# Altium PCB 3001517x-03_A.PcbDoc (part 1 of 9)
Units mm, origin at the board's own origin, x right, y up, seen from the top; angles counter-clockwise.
Board outline 100 x 72 mm, 10 copper layers (Top, GND_2, Signal_3, Signal_4, PWR_5, GND_6, Signal_7, Signal_8, GND_9, Bottom), stack 1.6 mm thick; 602 components, 497 nets, 2372 pads, 1602 vias.
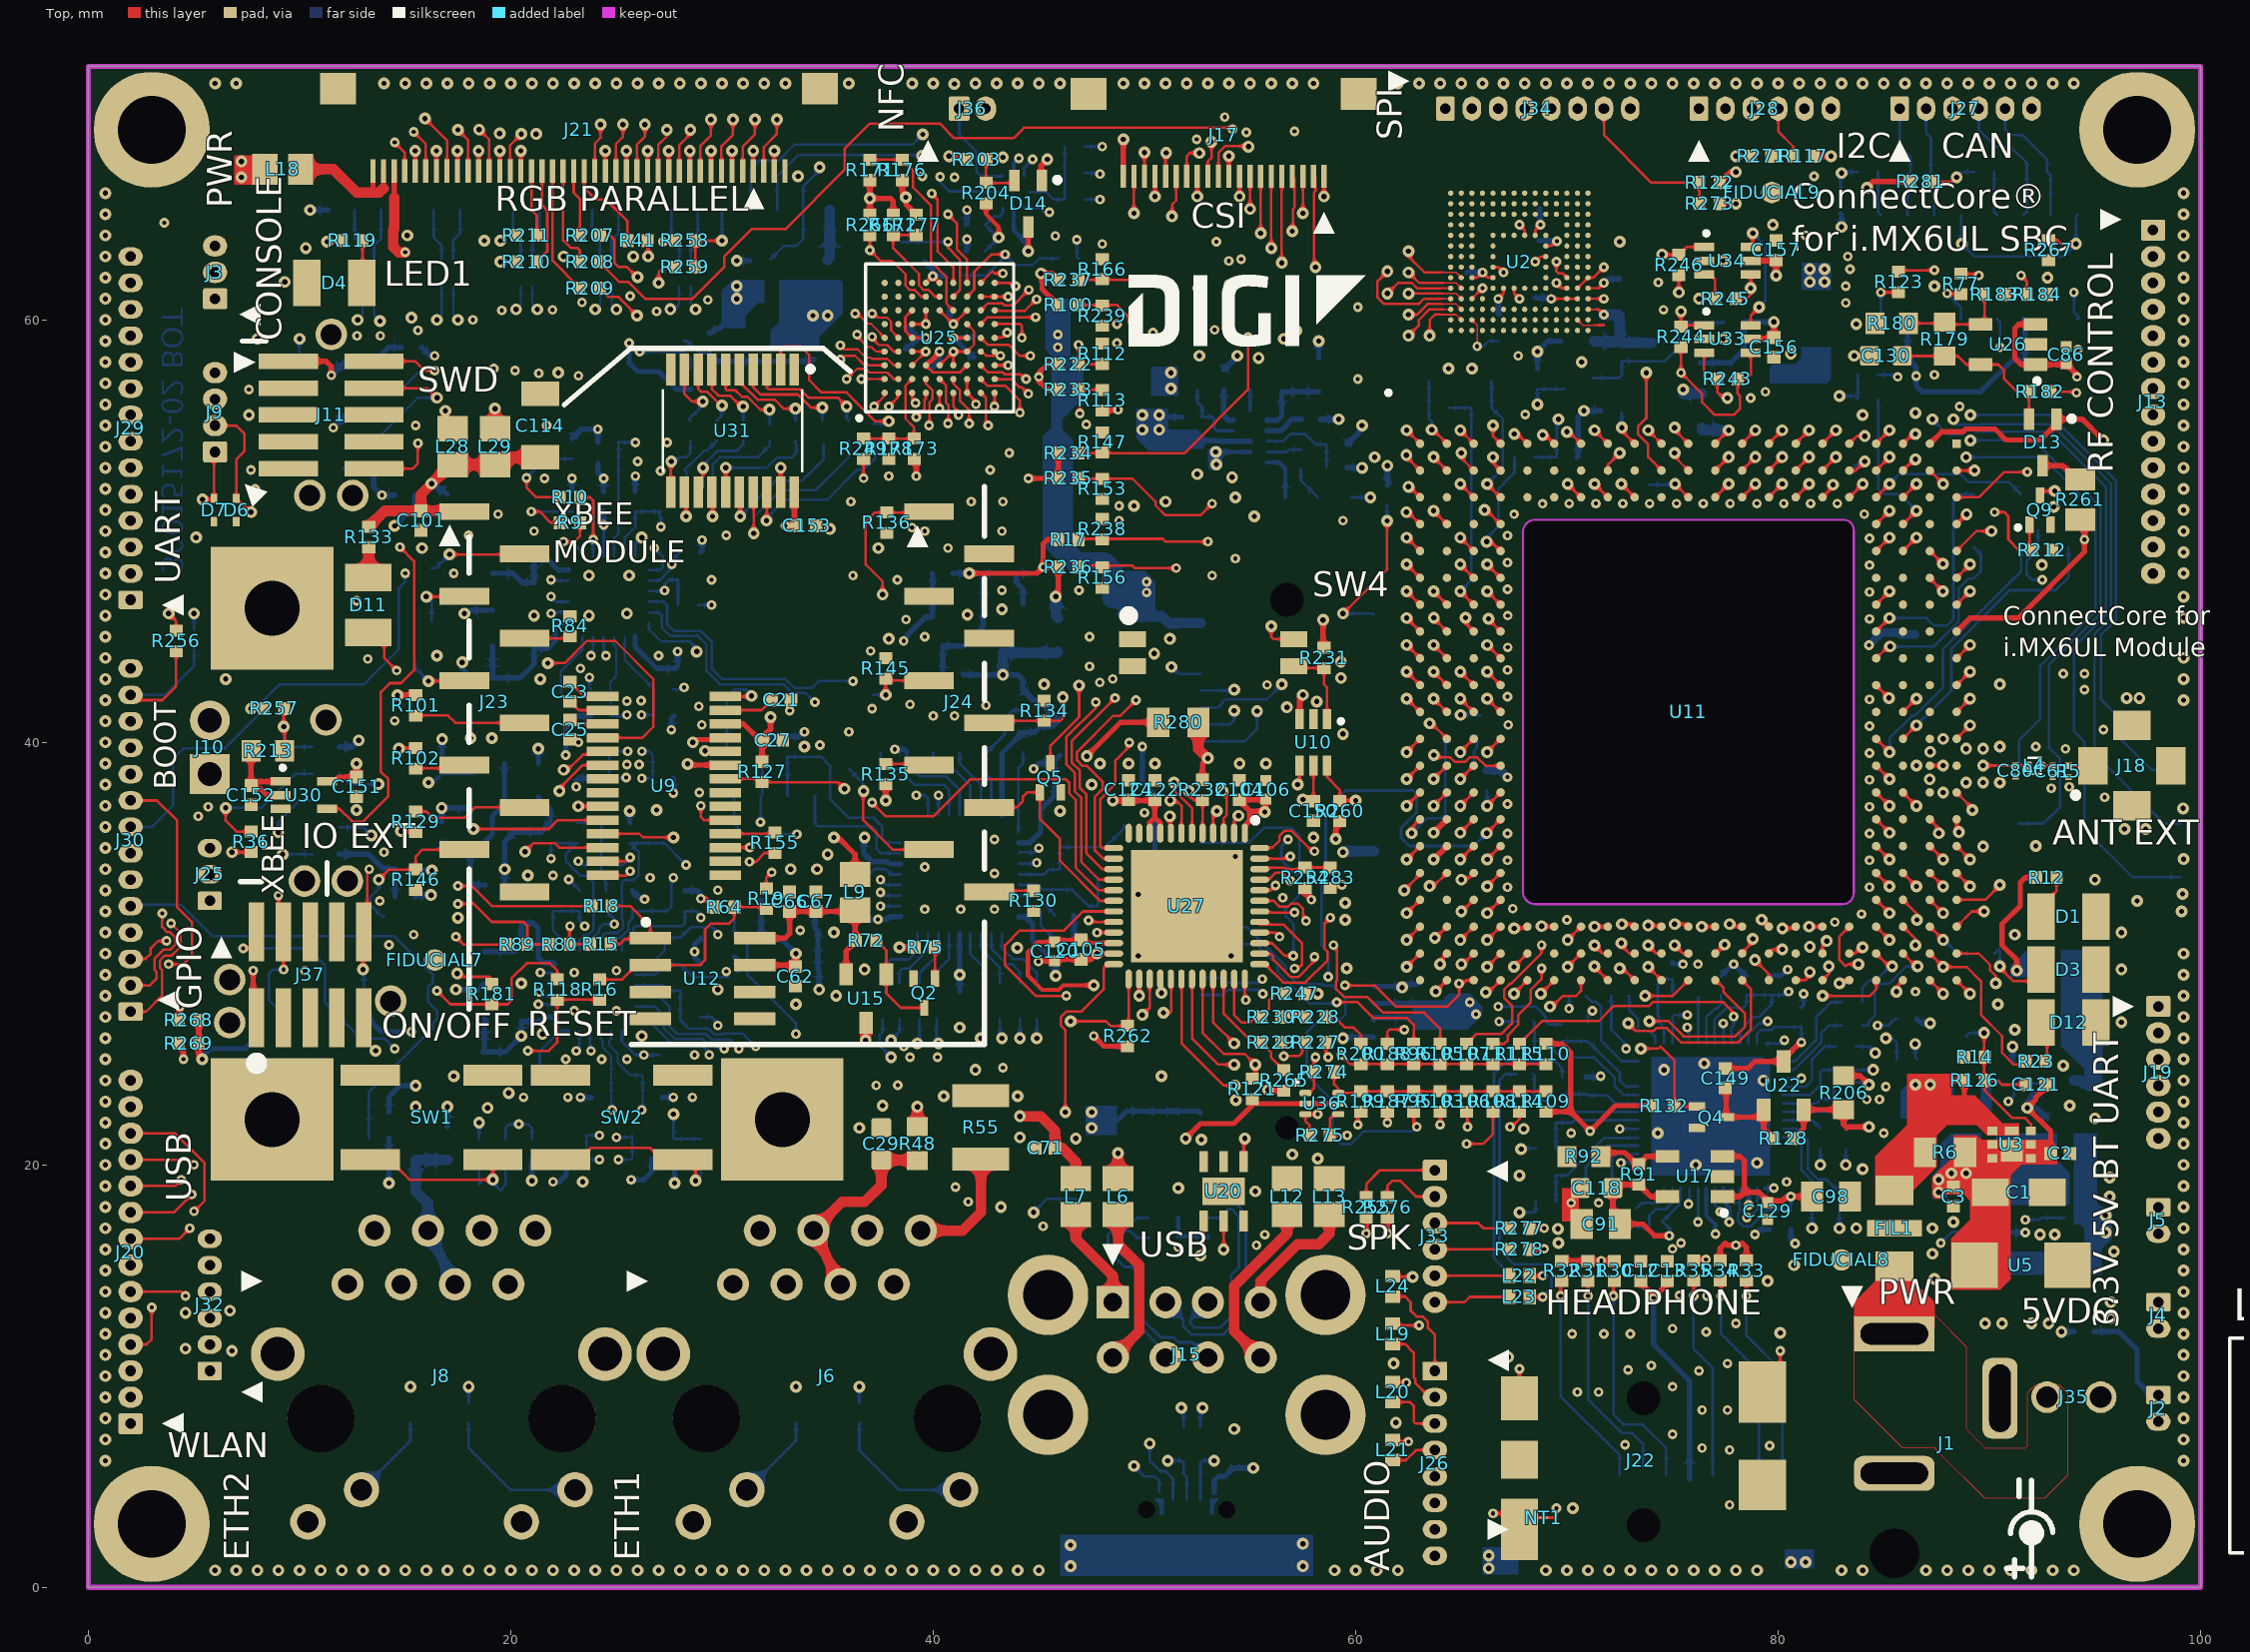
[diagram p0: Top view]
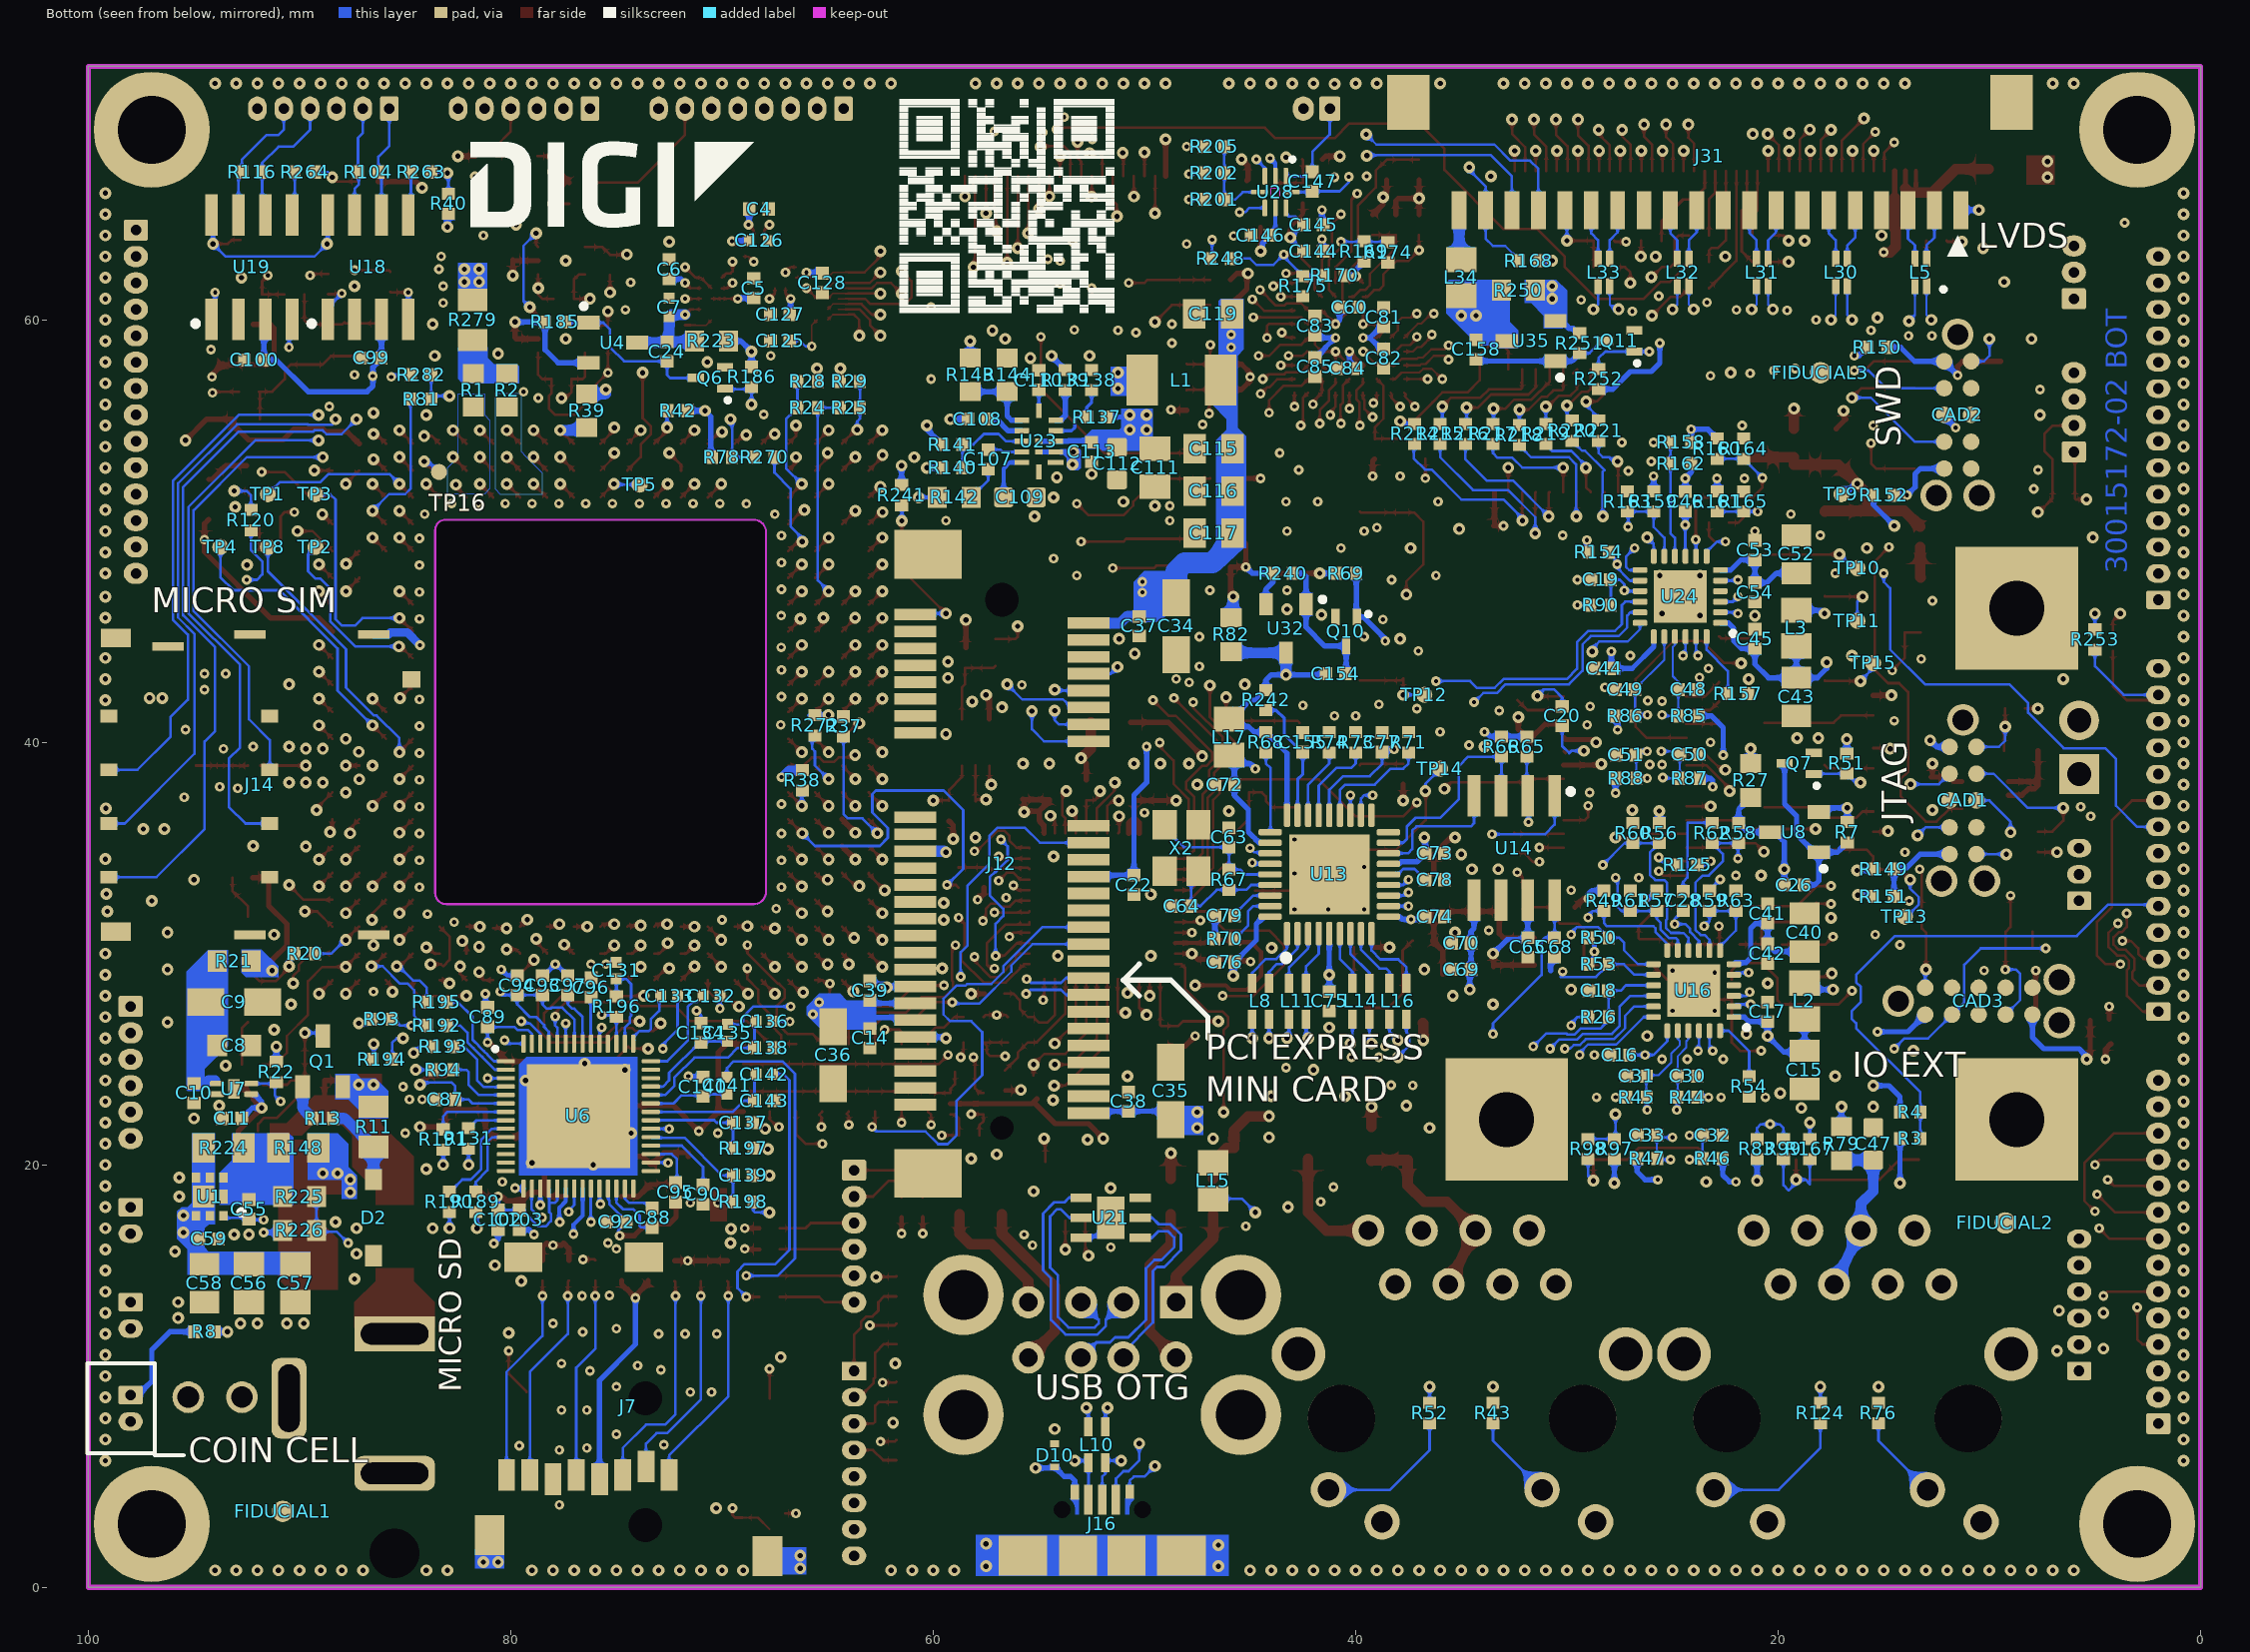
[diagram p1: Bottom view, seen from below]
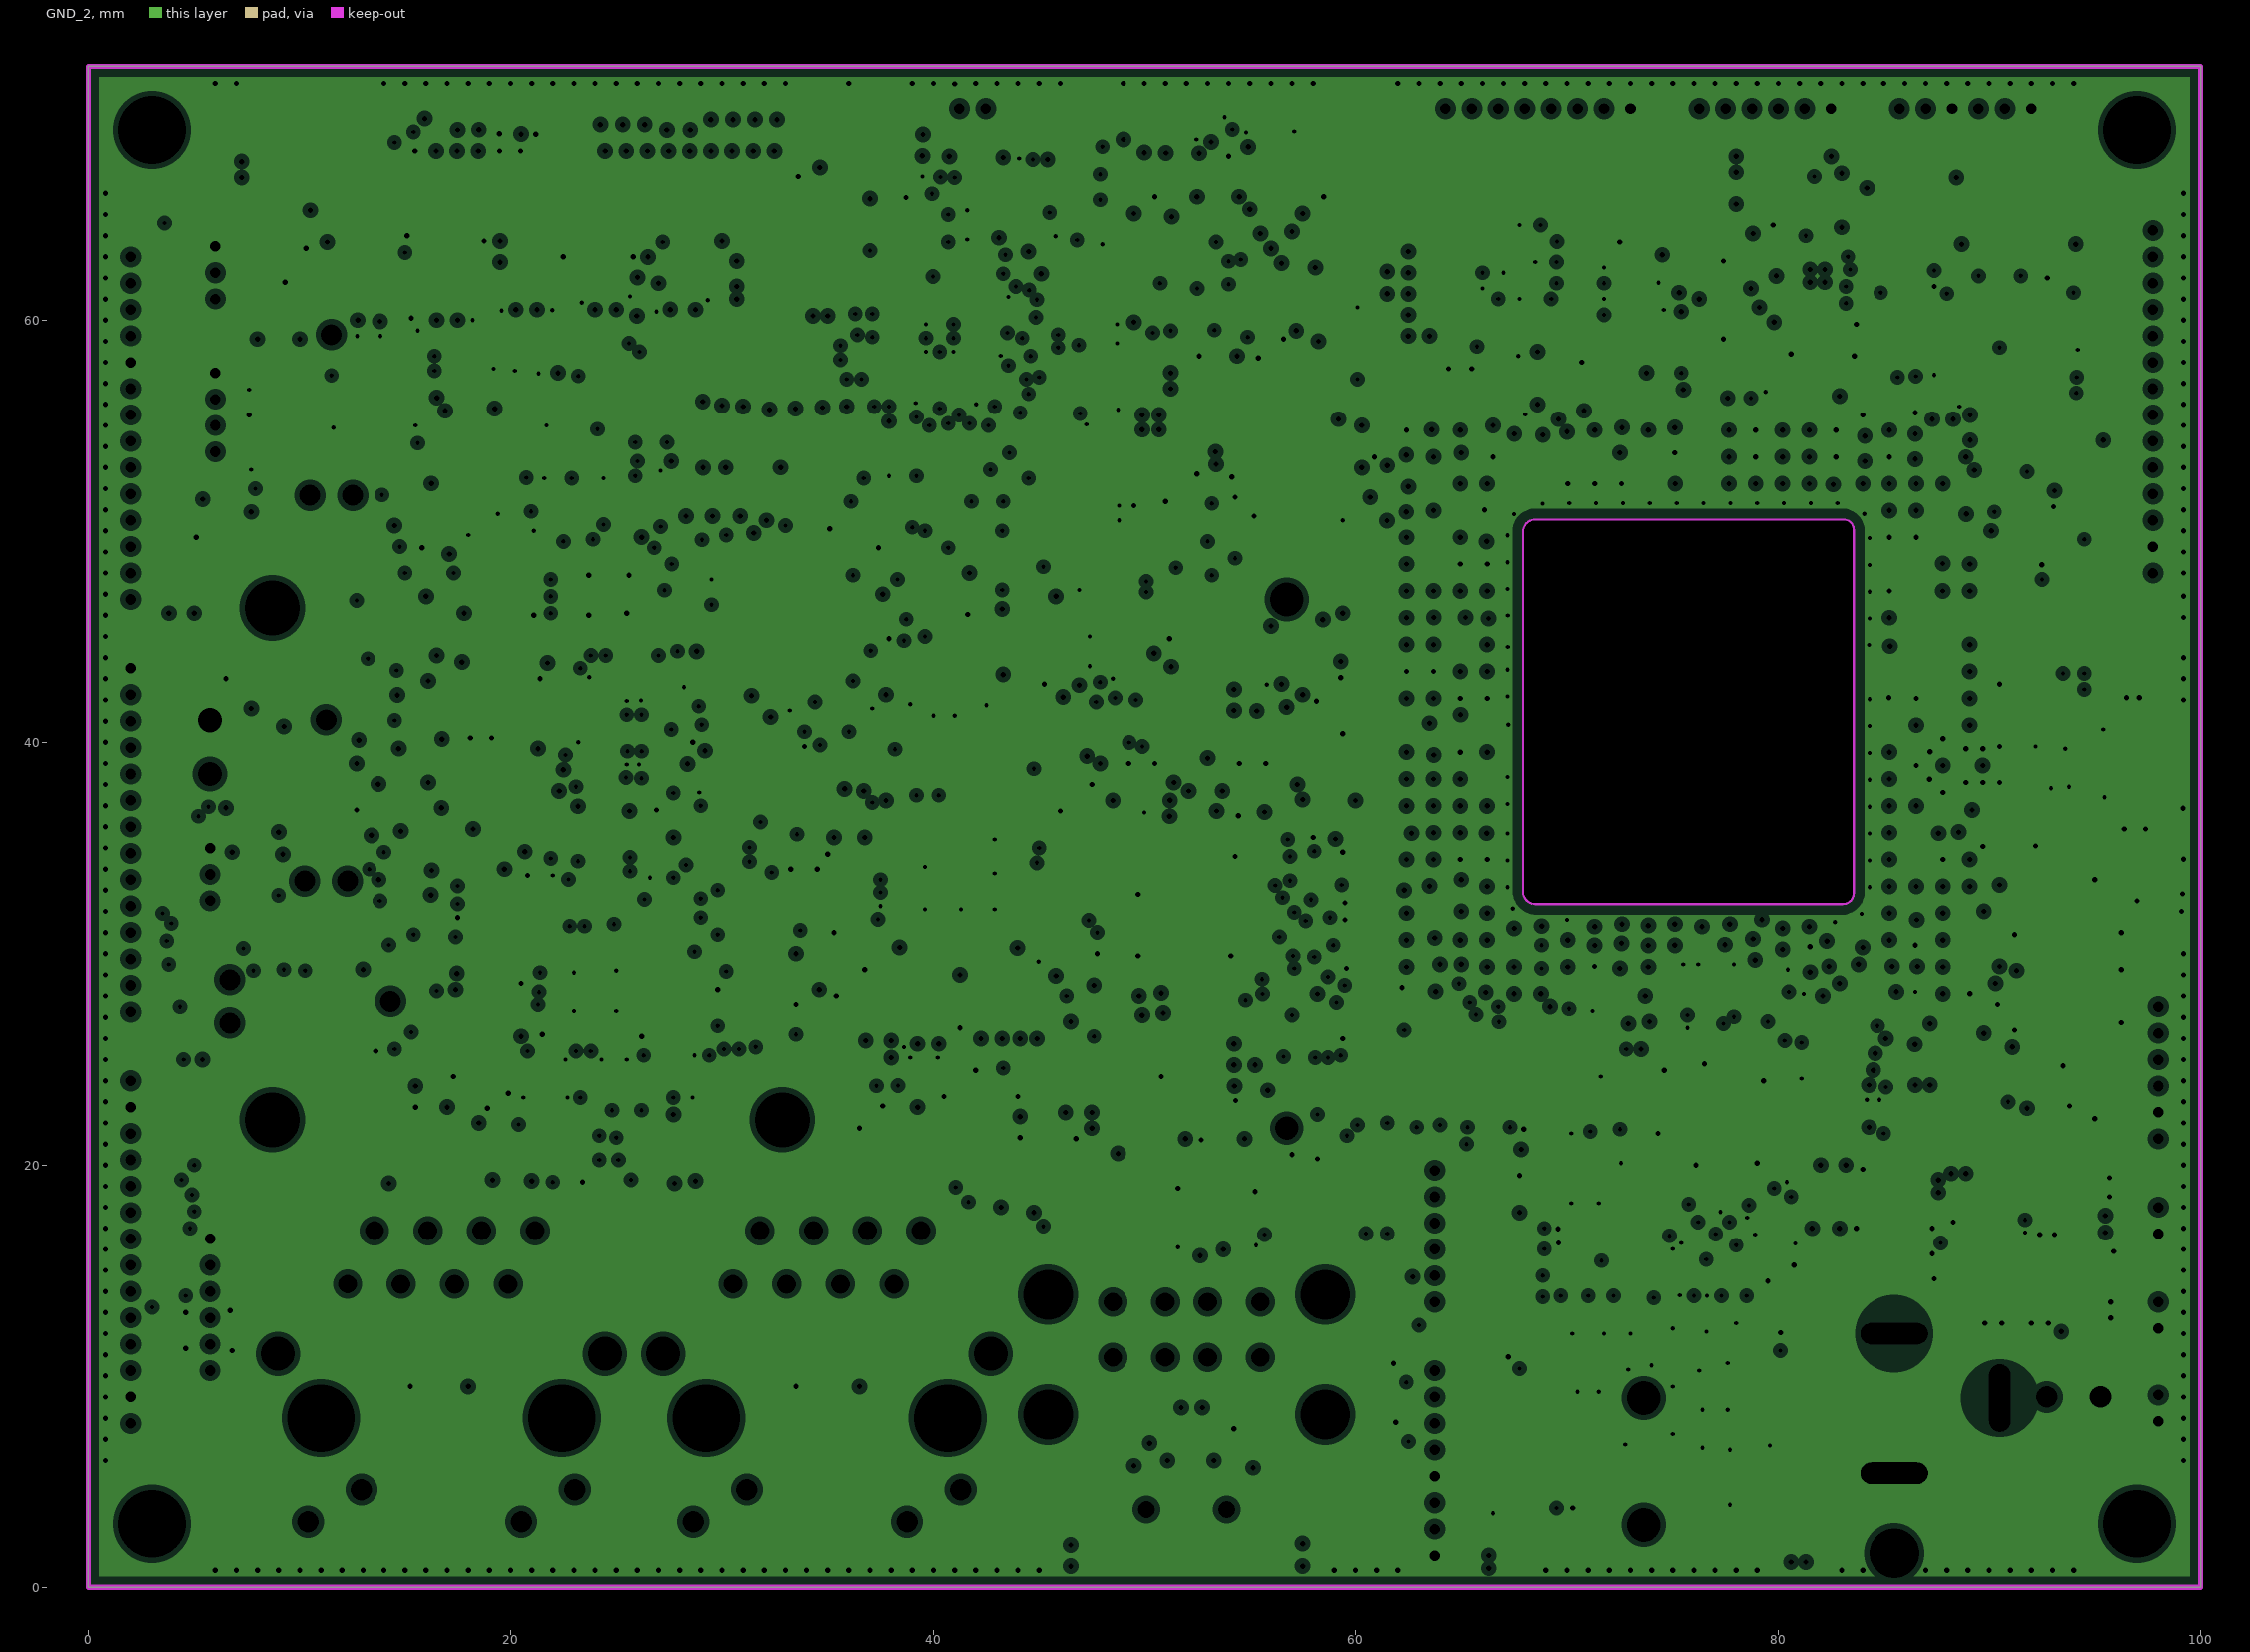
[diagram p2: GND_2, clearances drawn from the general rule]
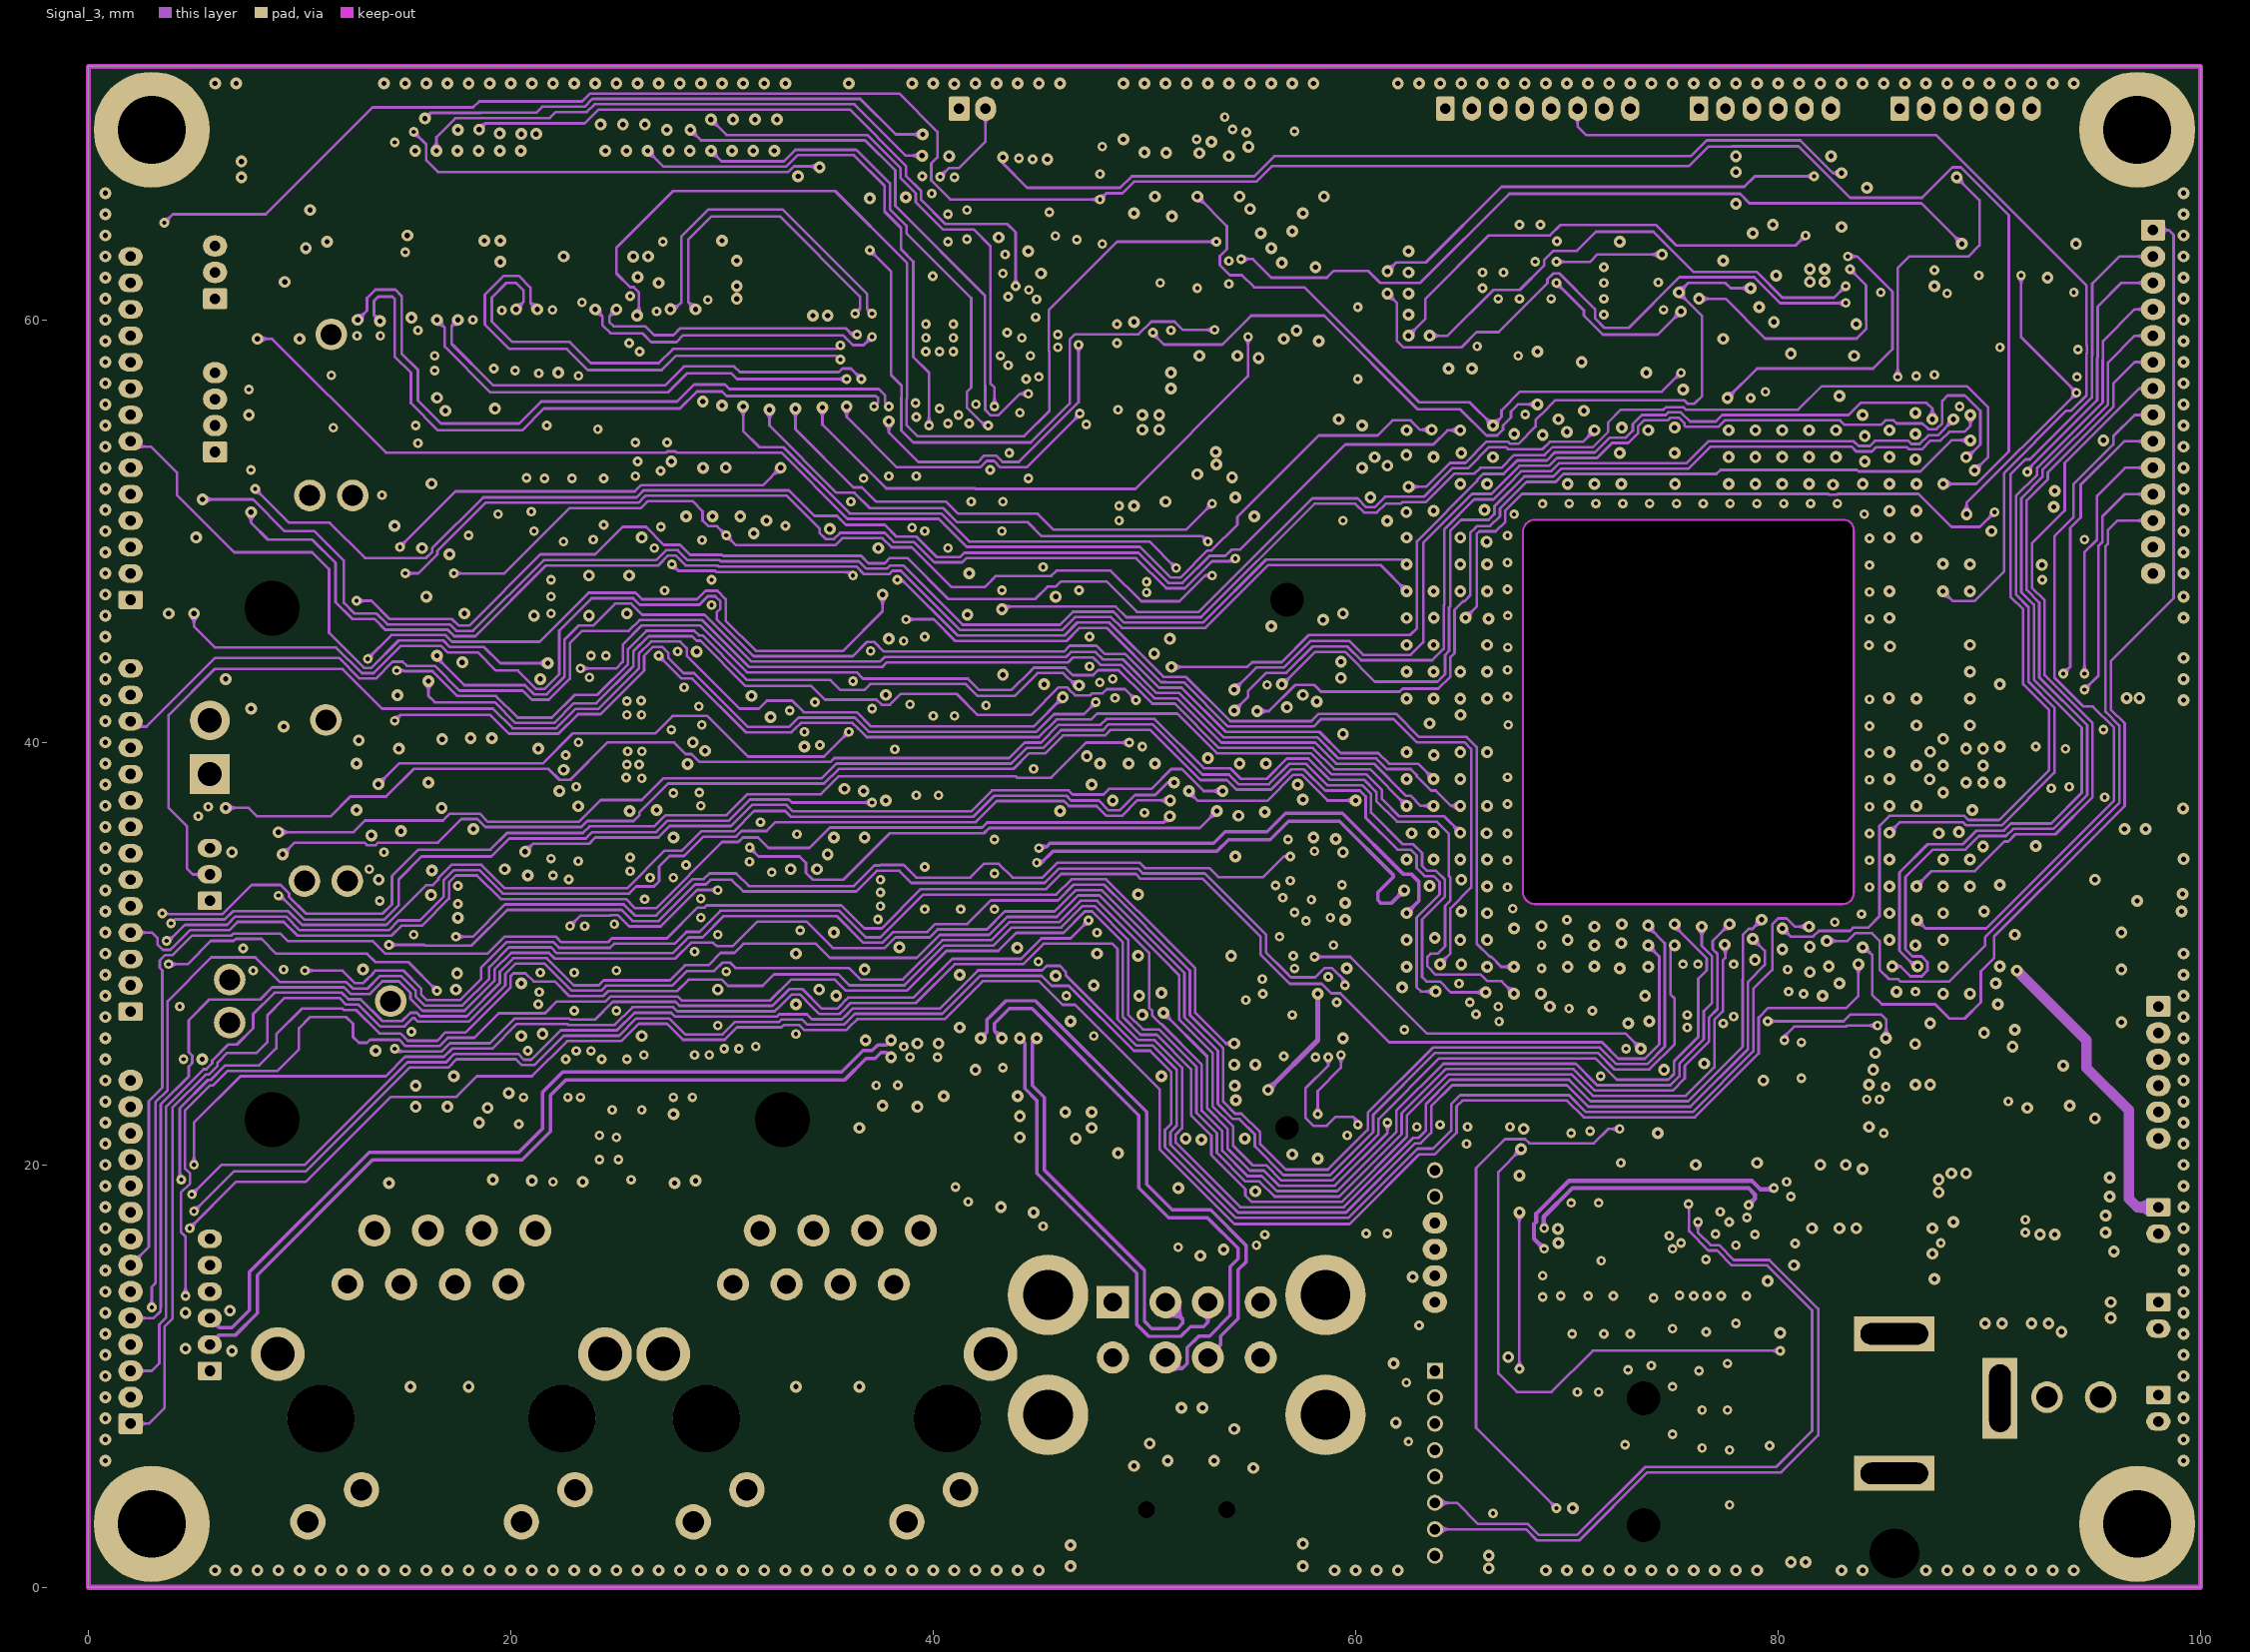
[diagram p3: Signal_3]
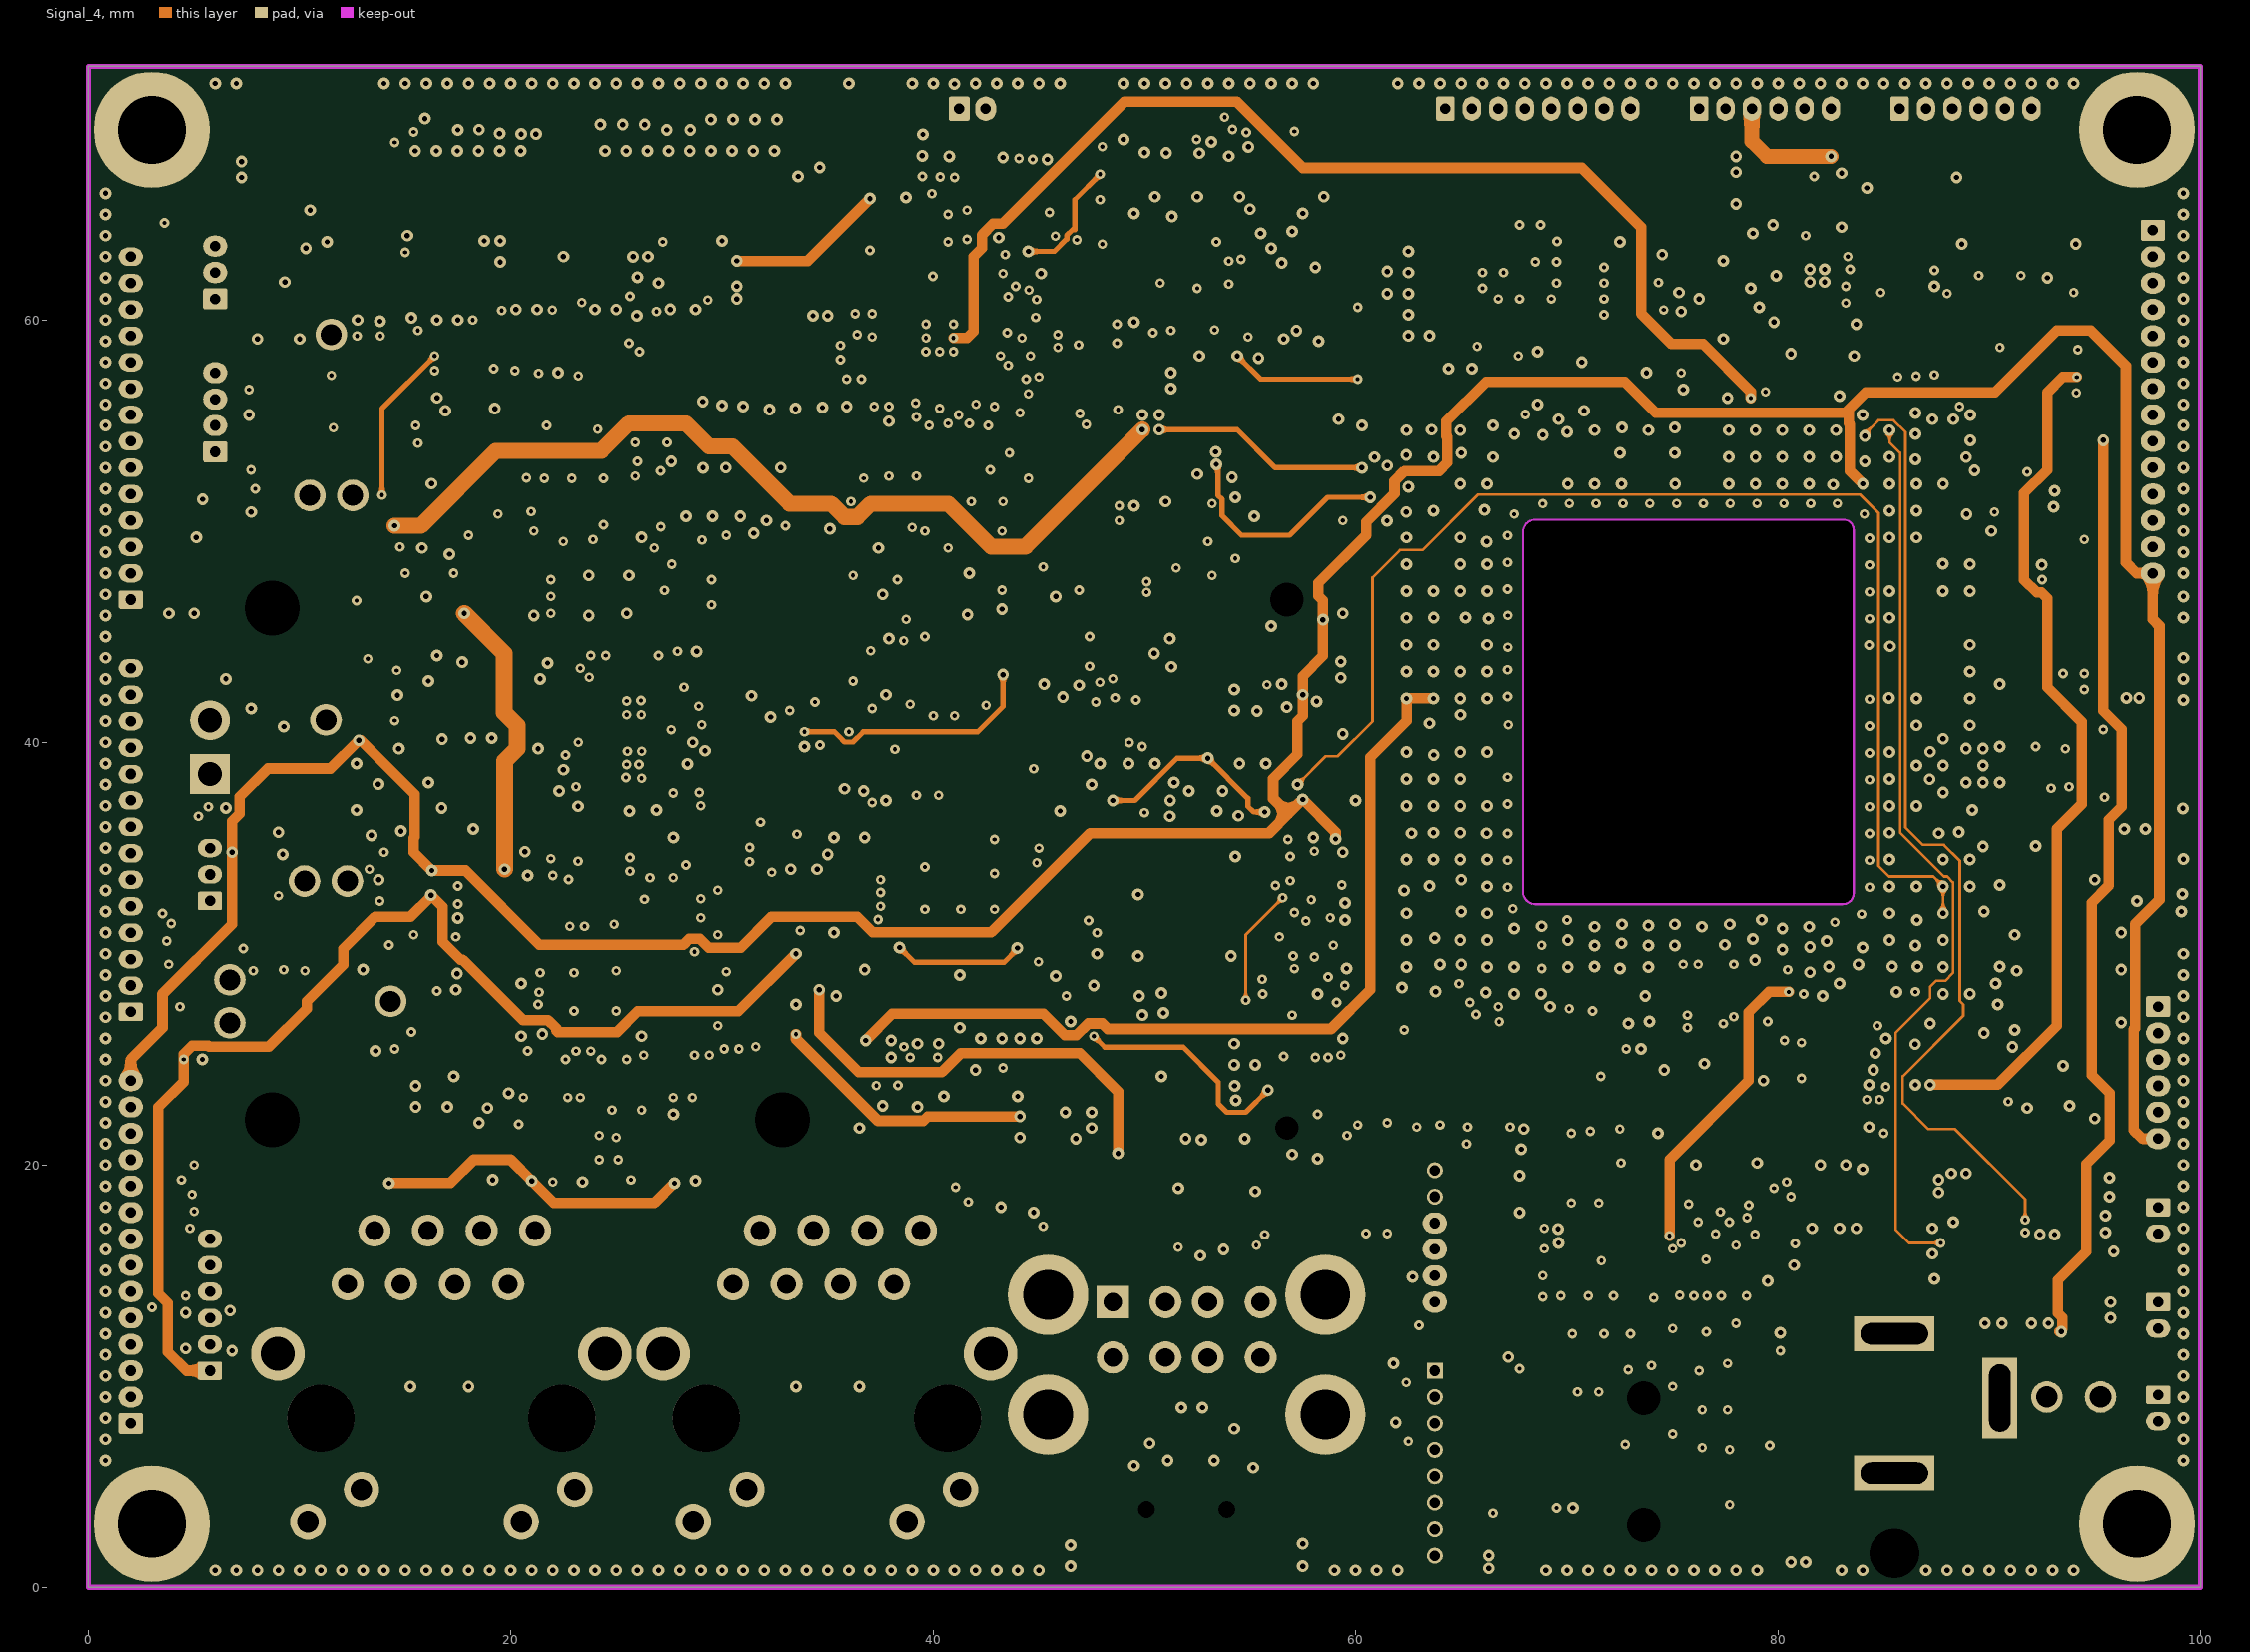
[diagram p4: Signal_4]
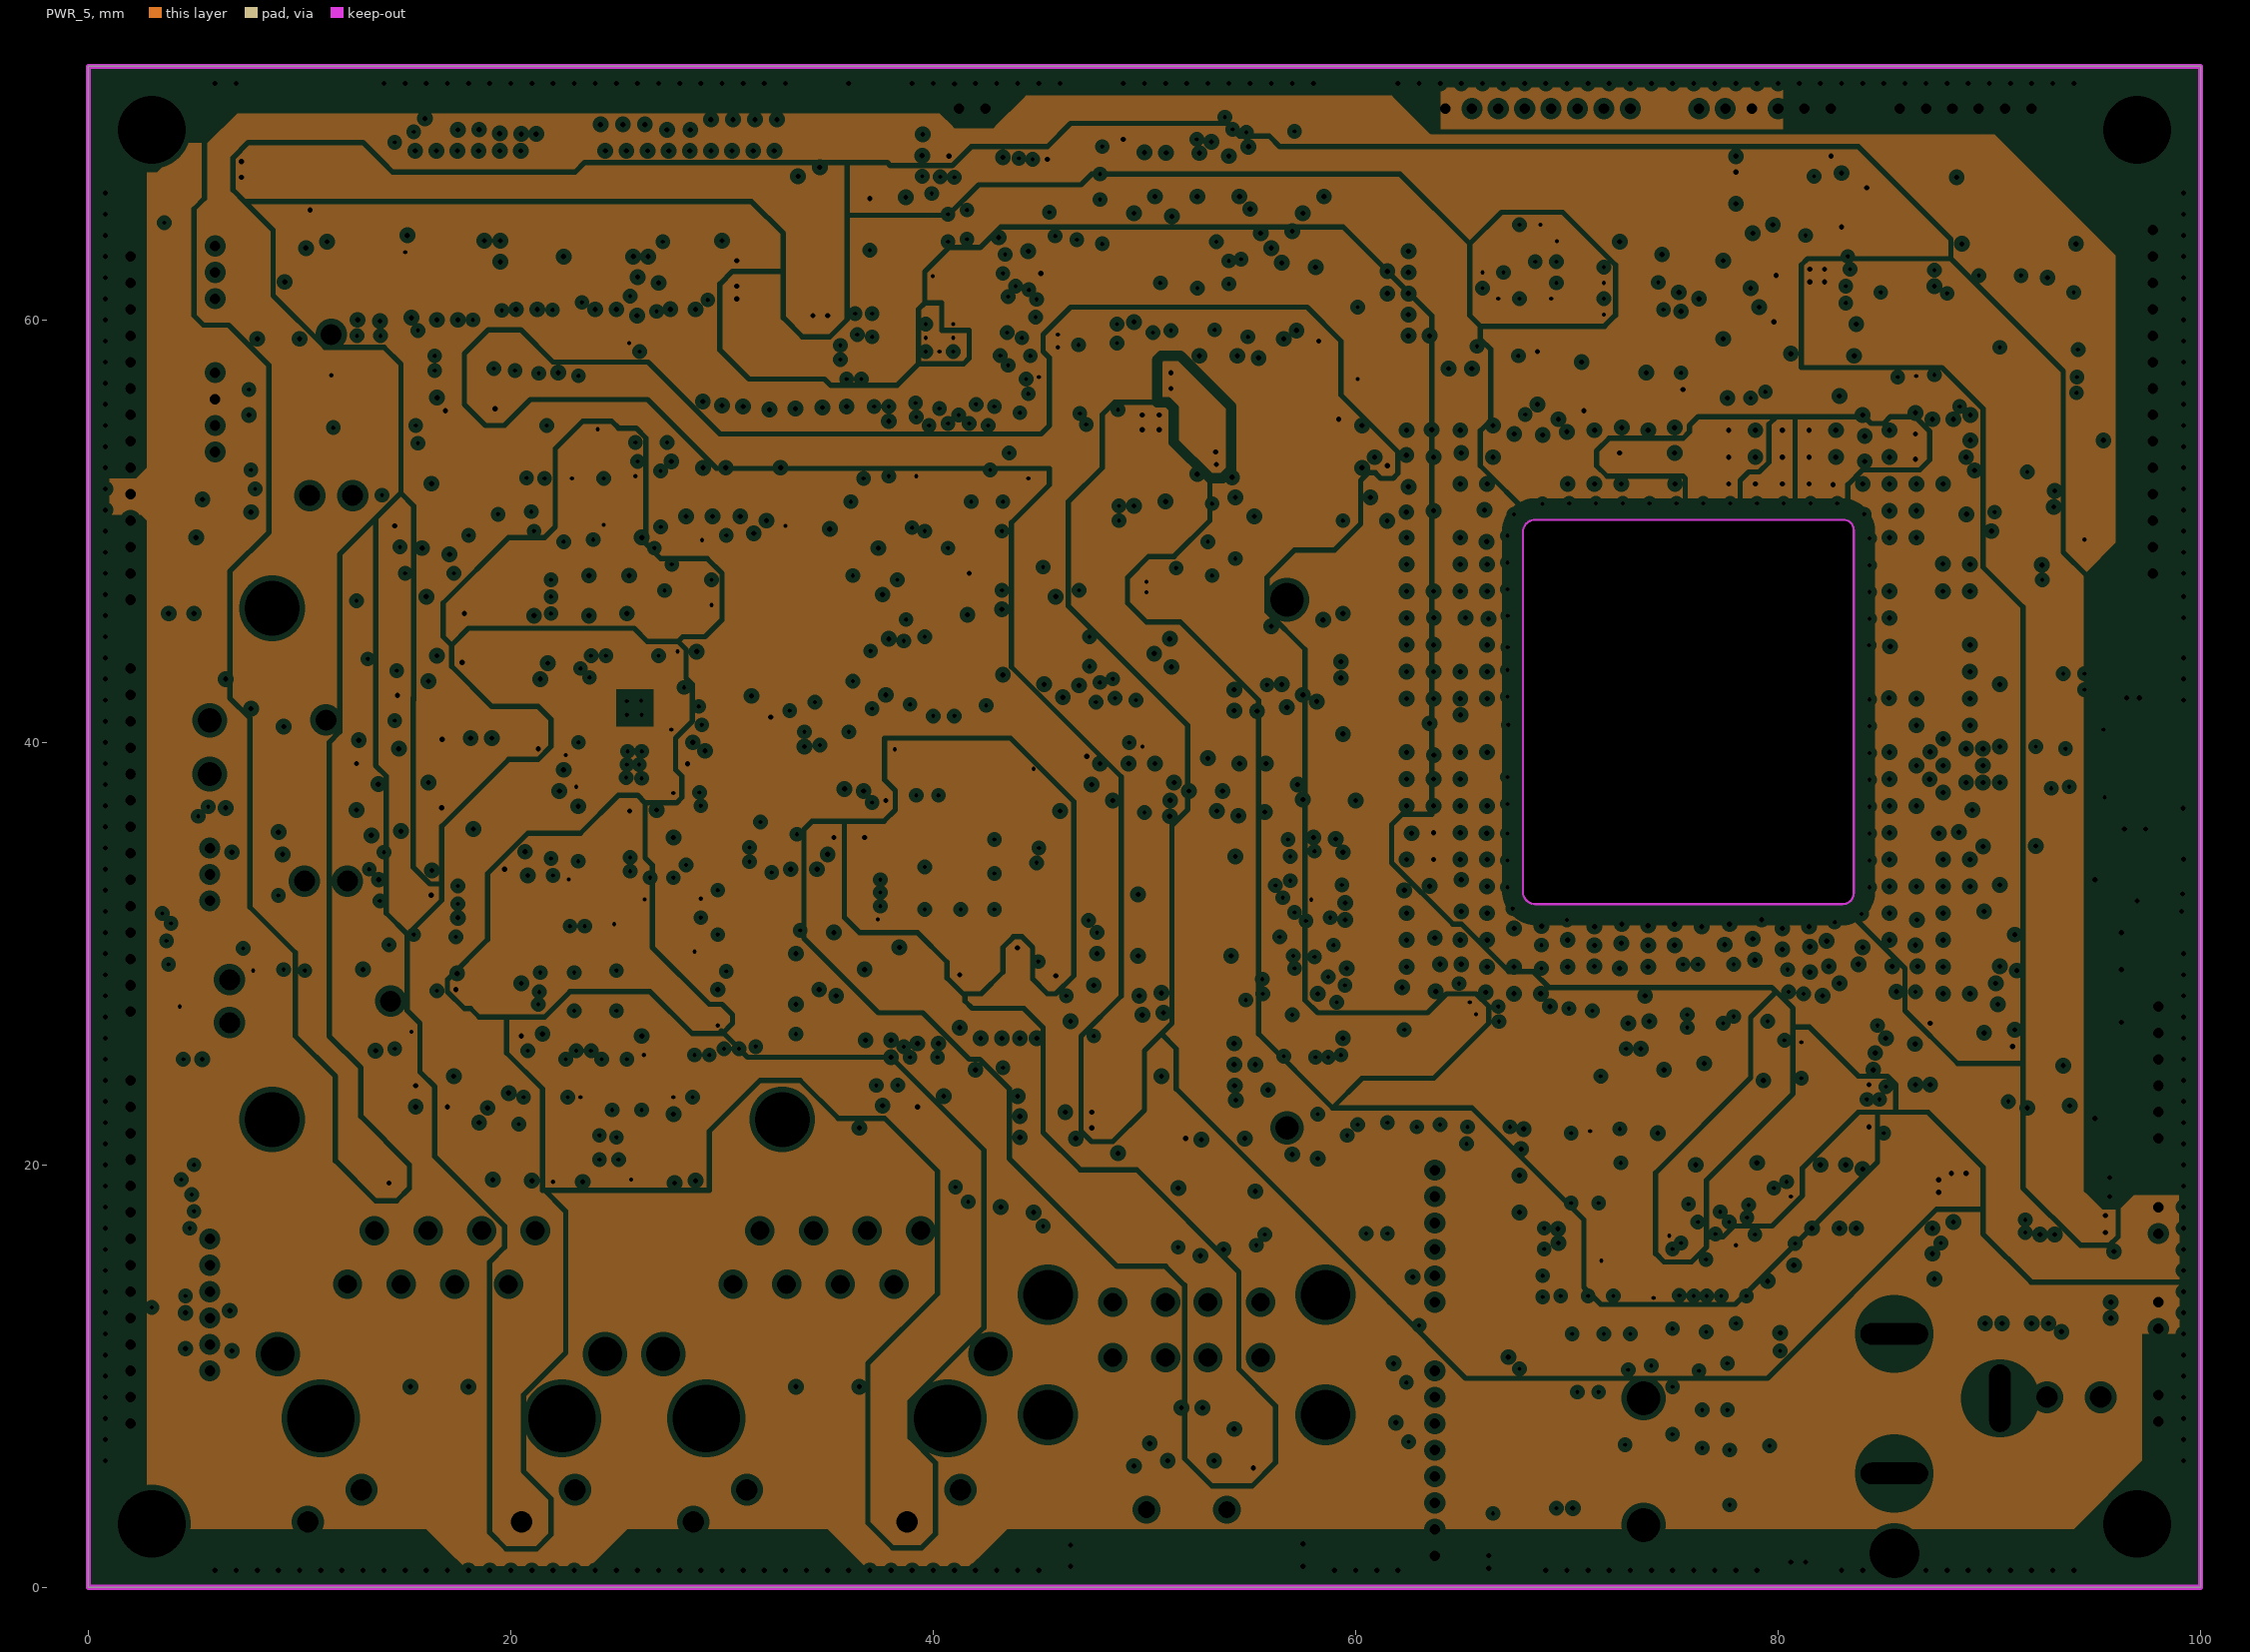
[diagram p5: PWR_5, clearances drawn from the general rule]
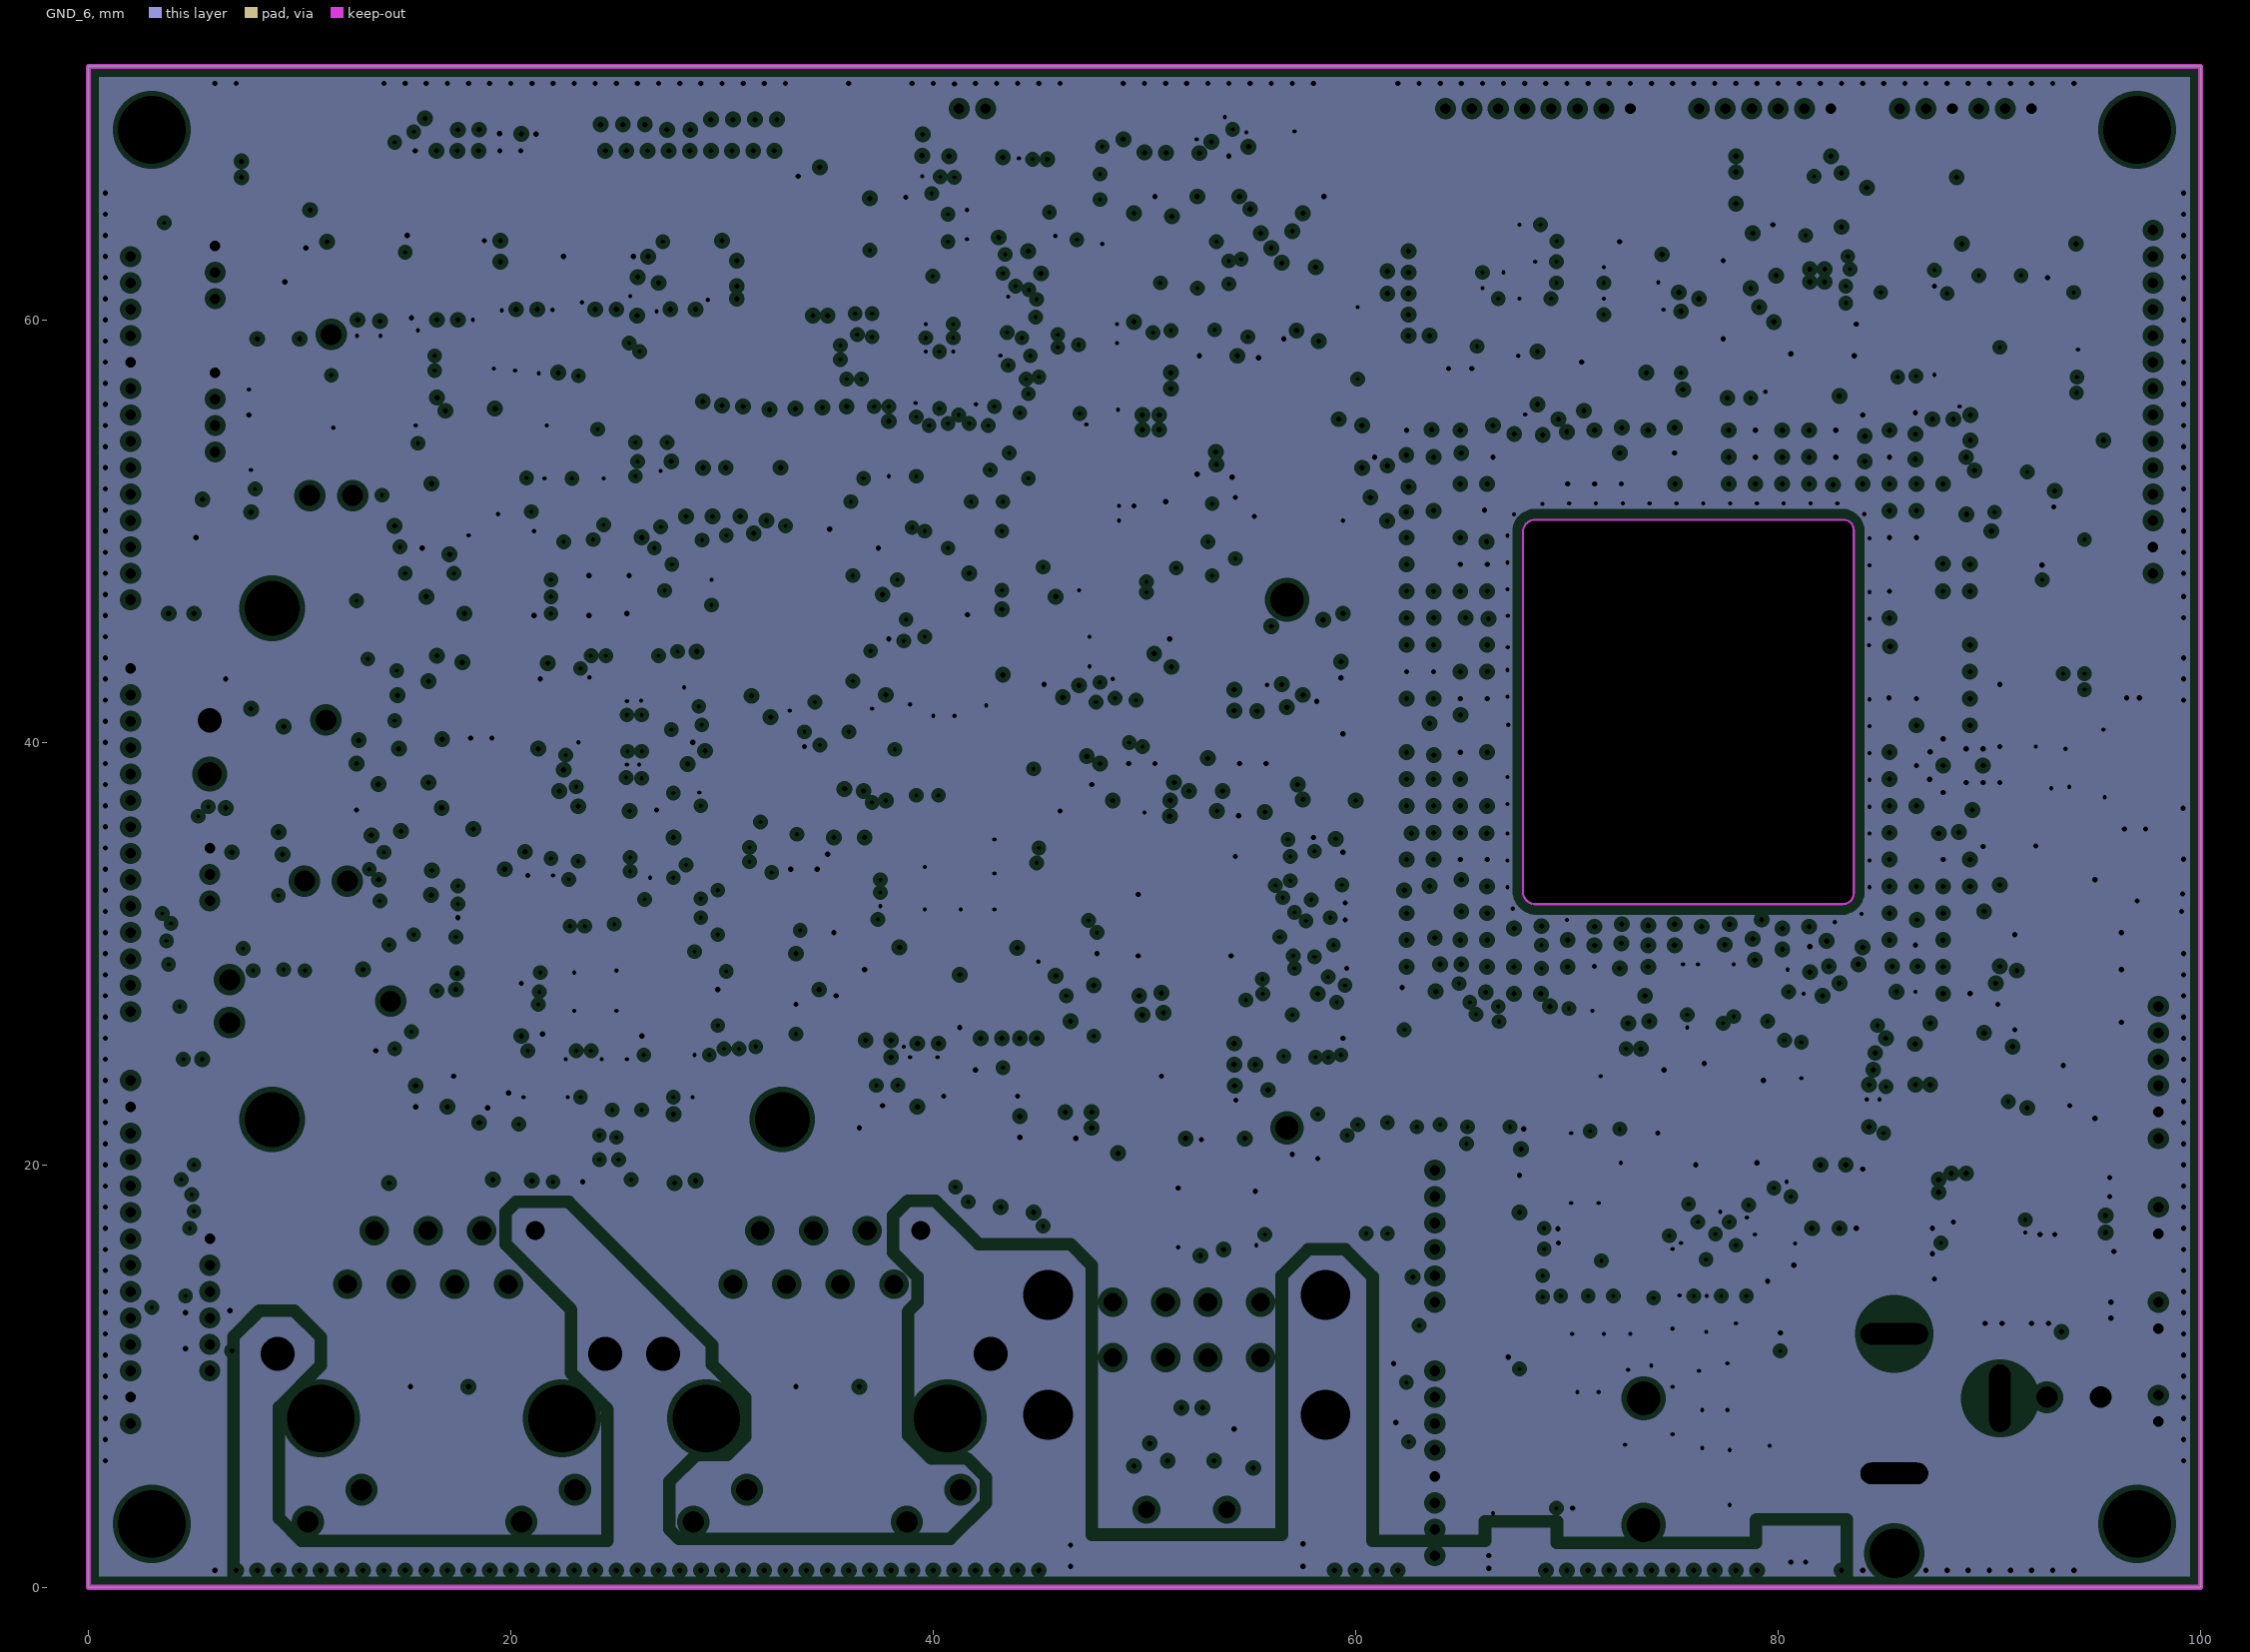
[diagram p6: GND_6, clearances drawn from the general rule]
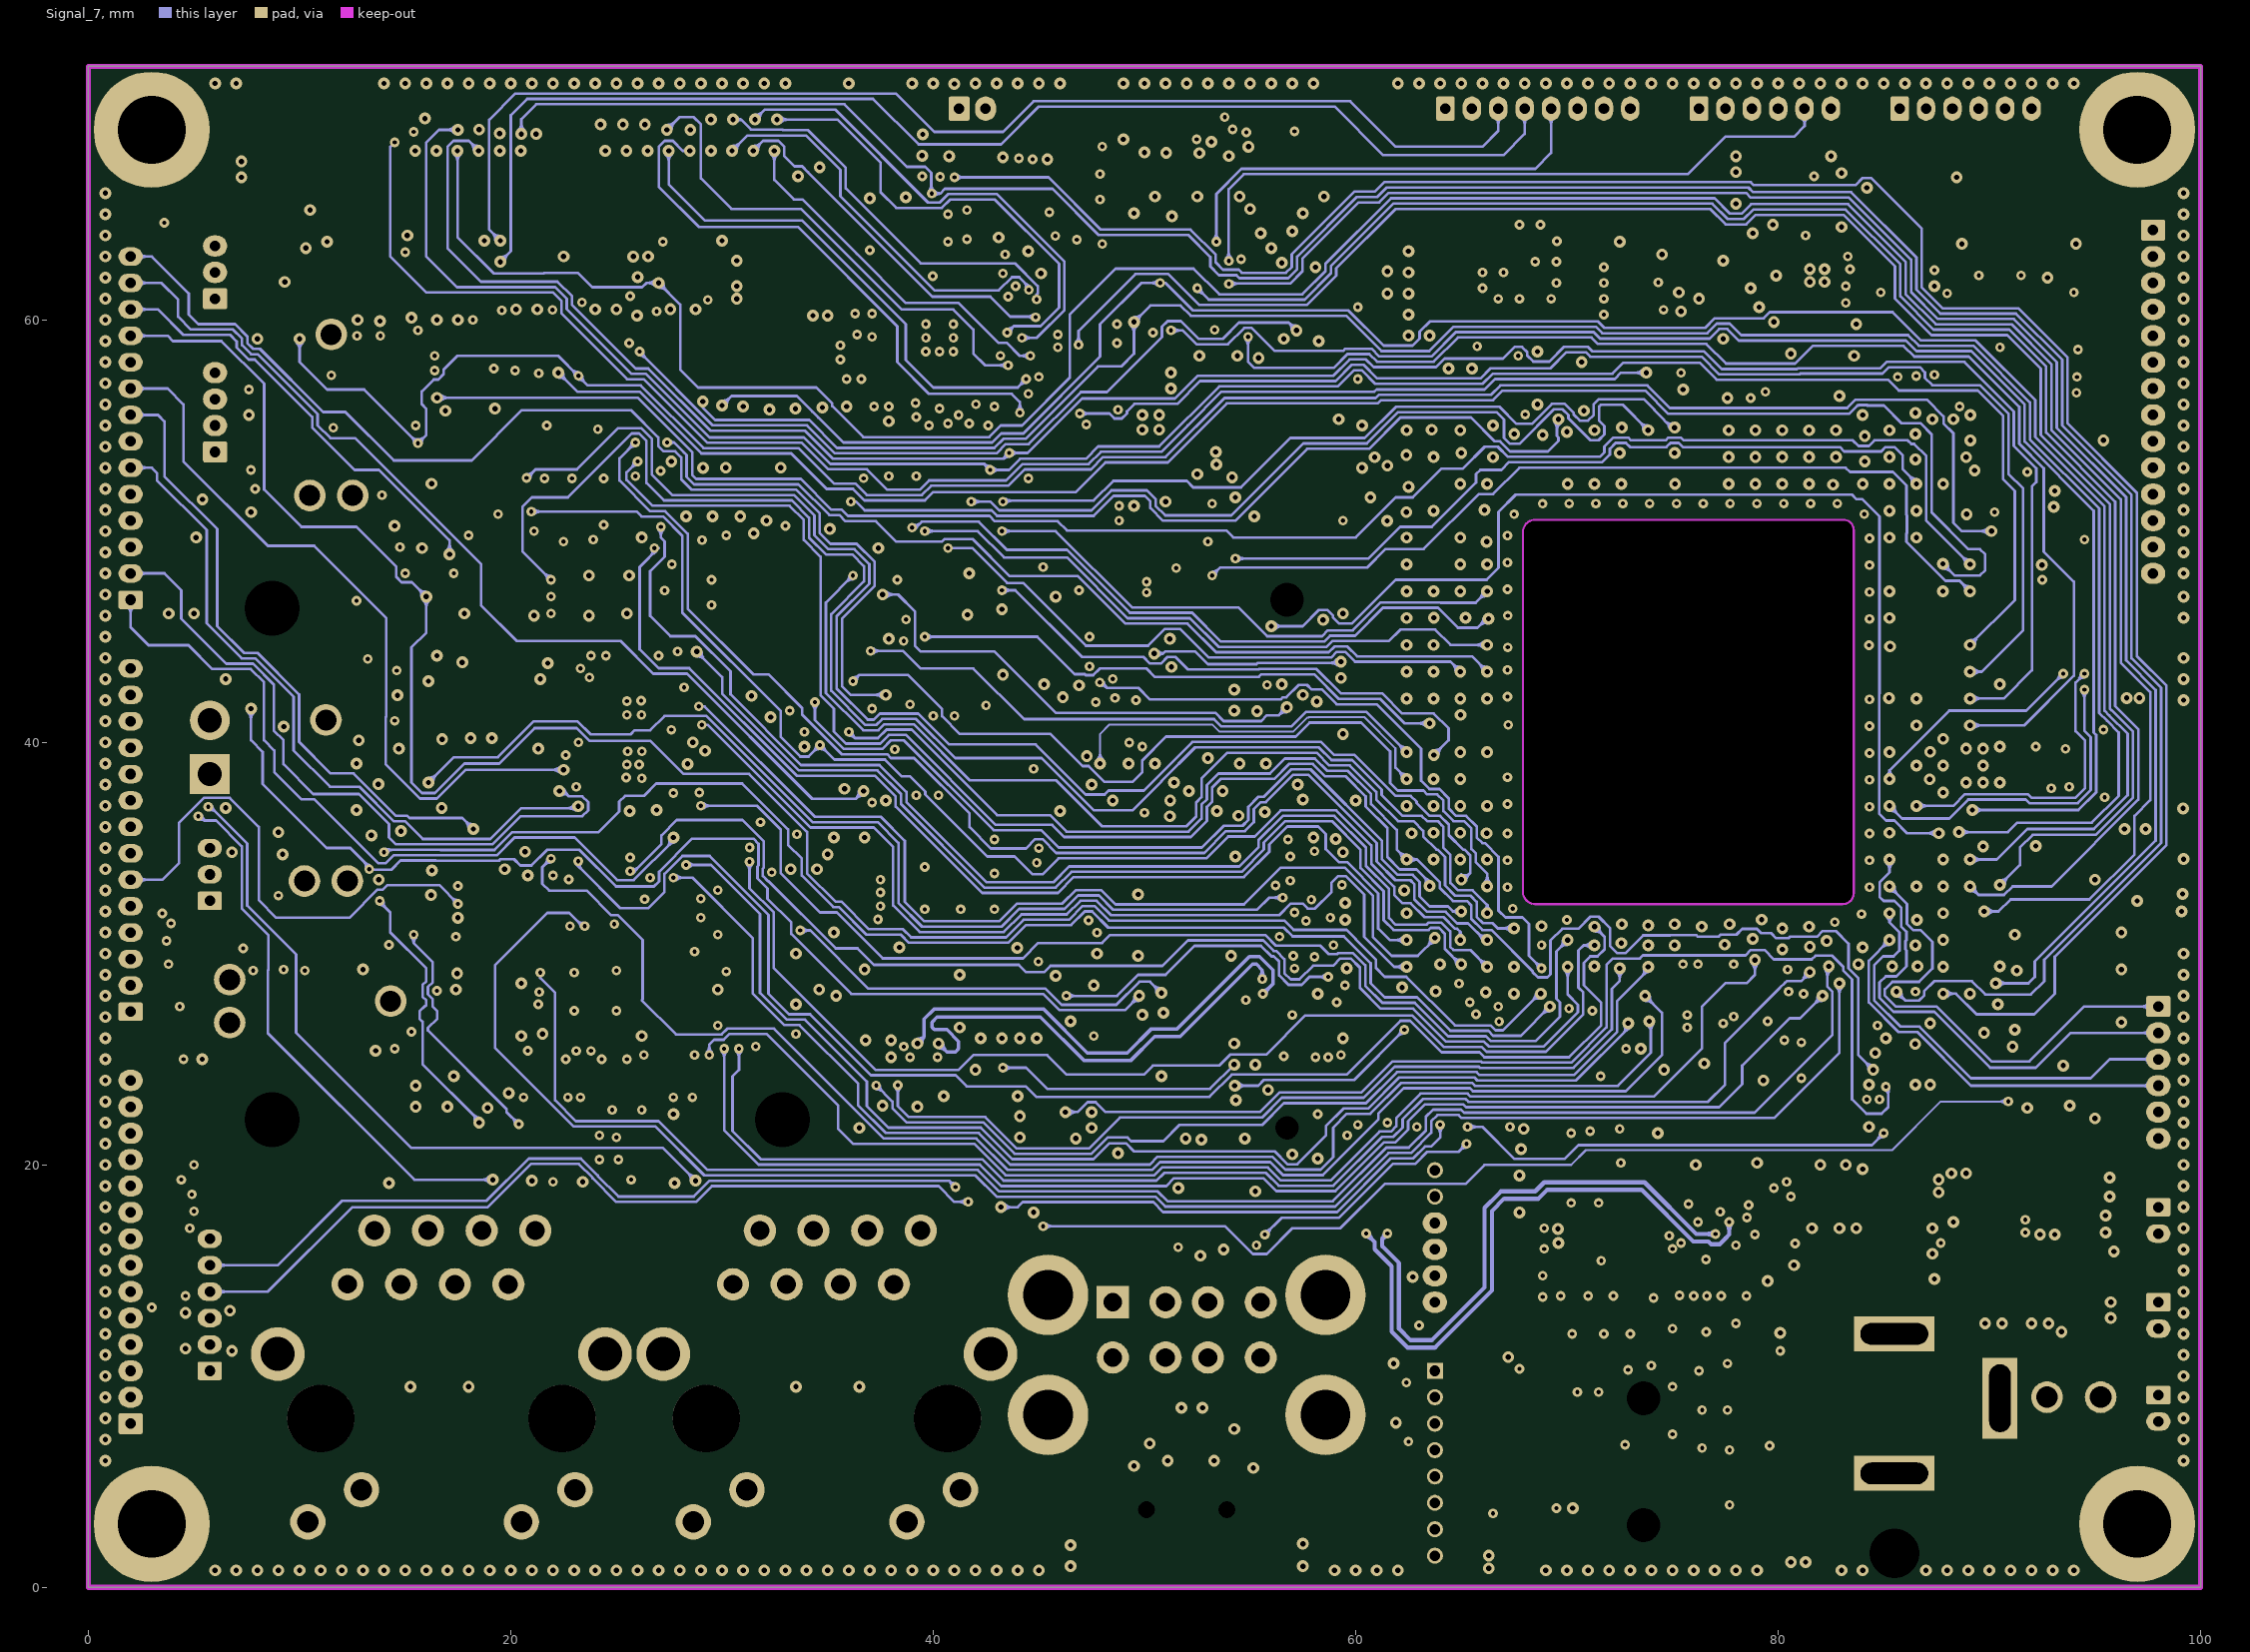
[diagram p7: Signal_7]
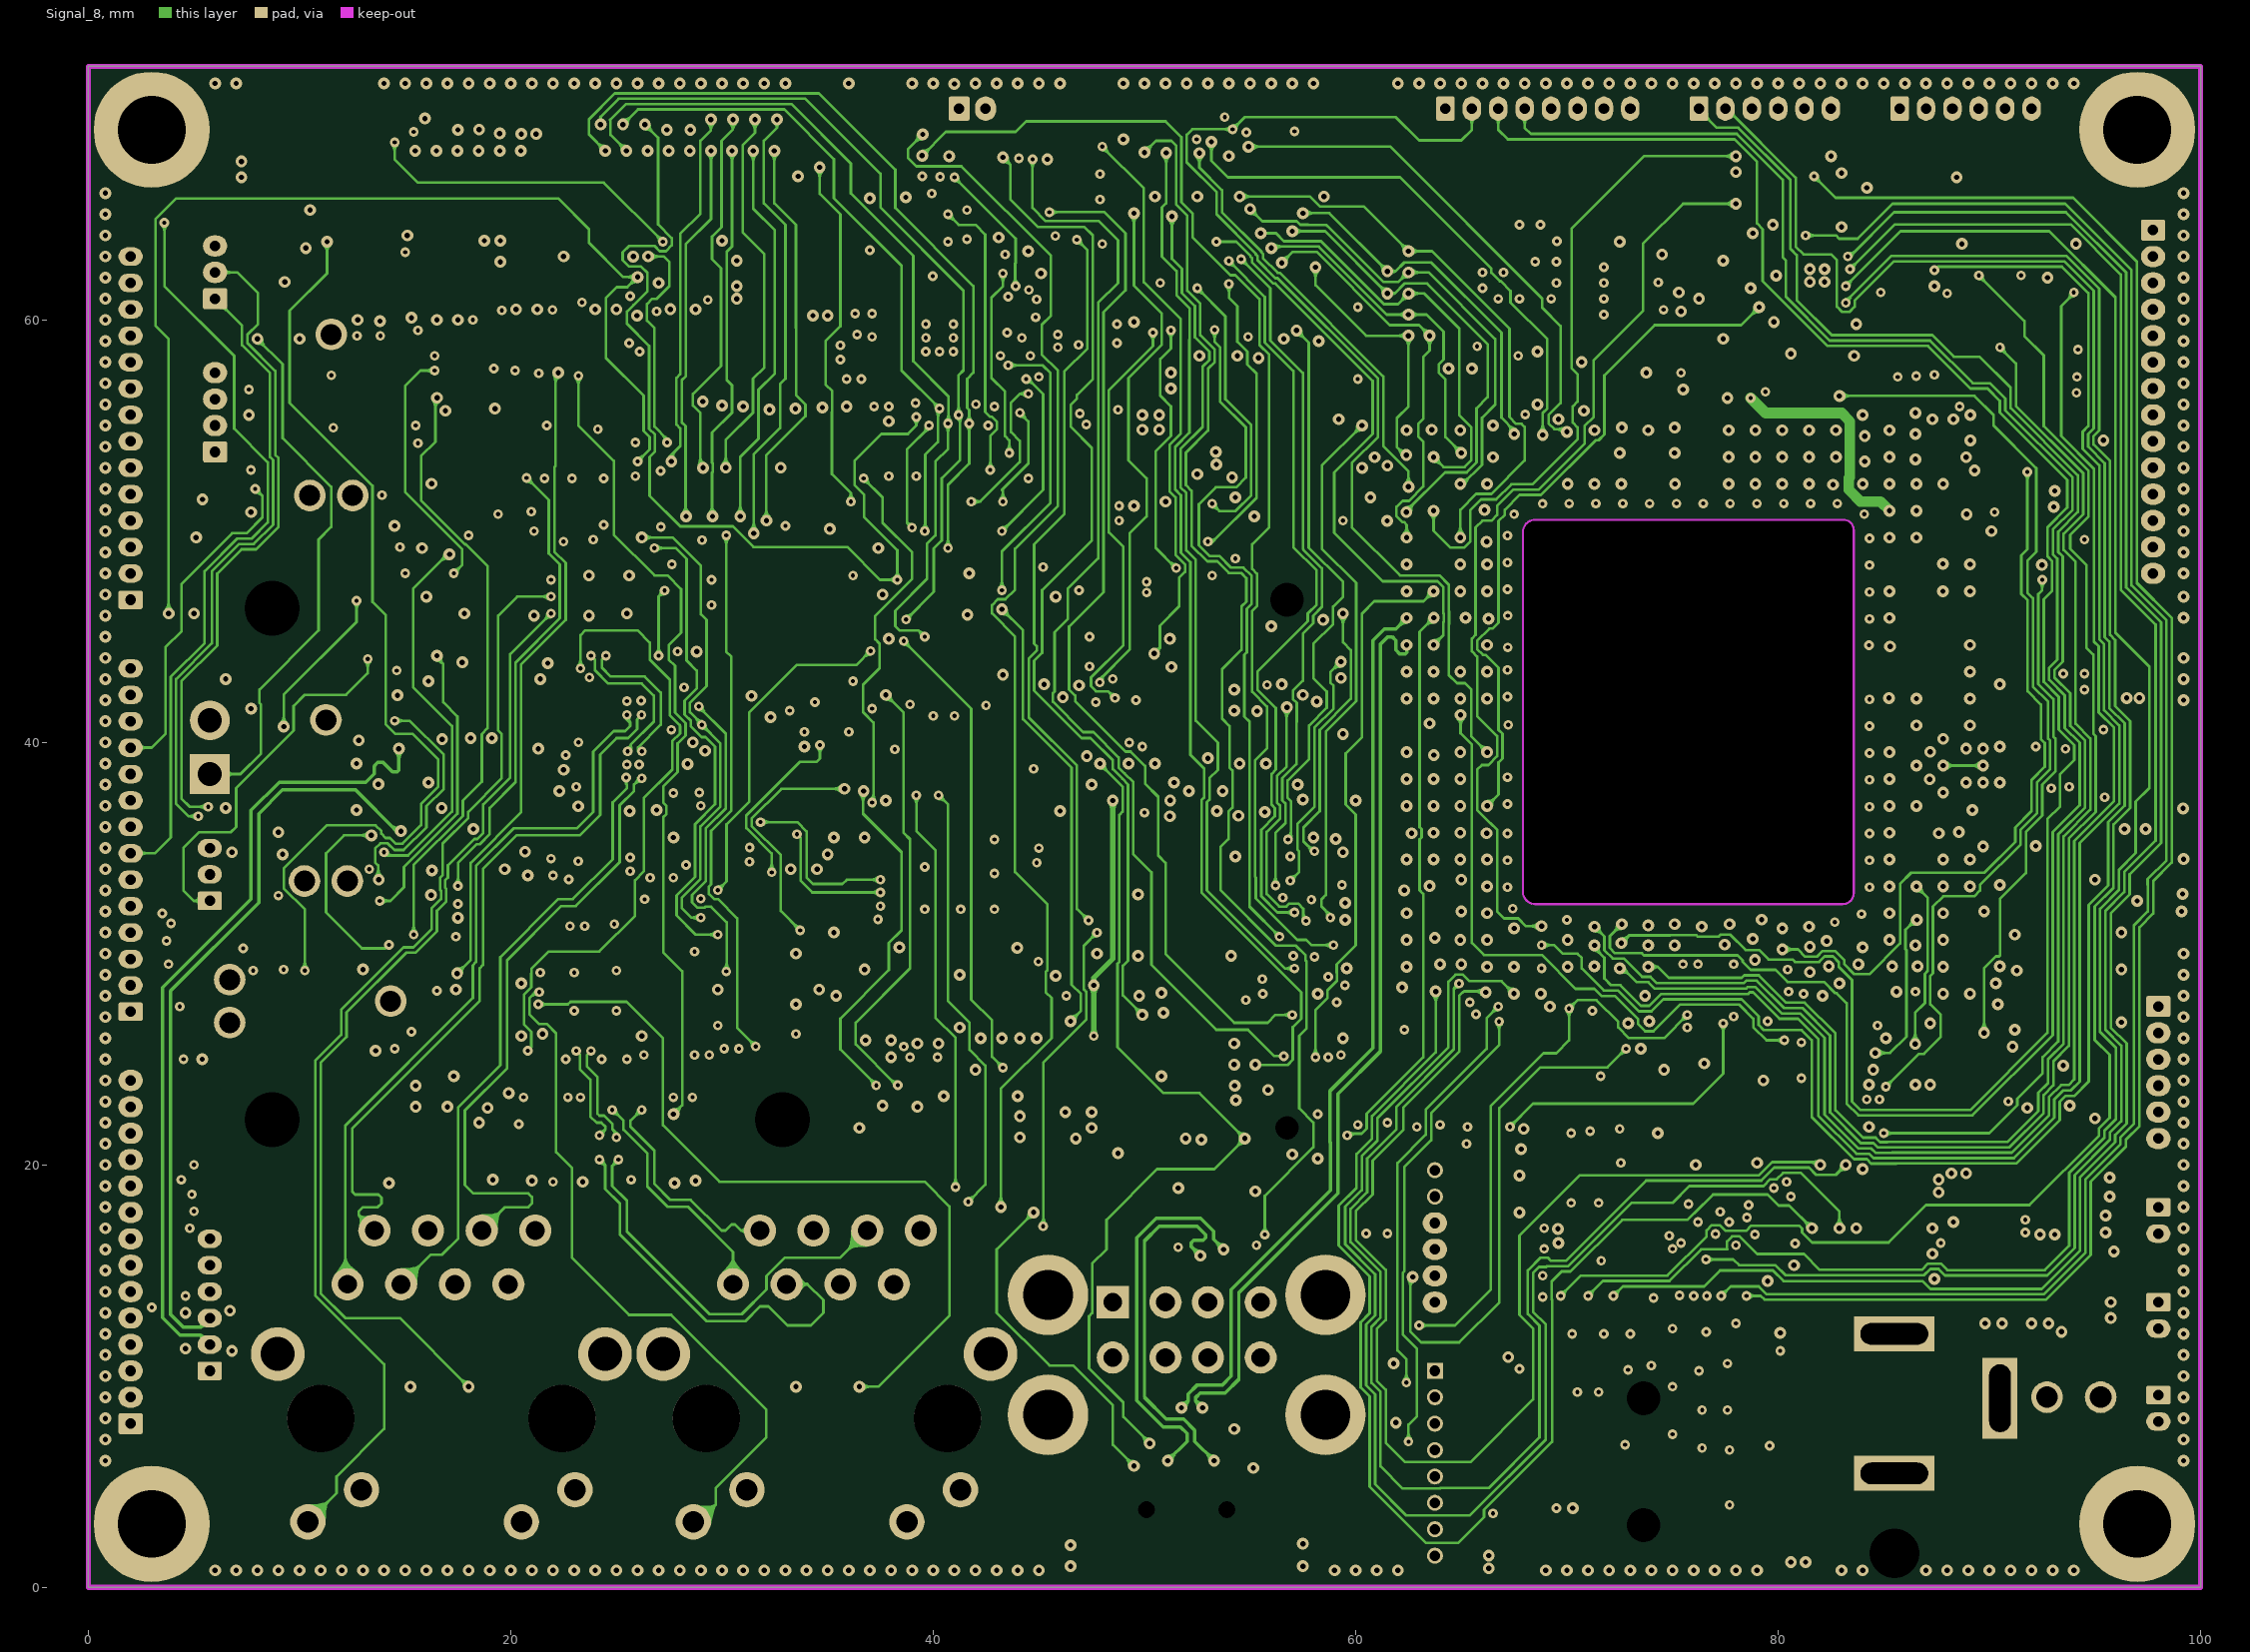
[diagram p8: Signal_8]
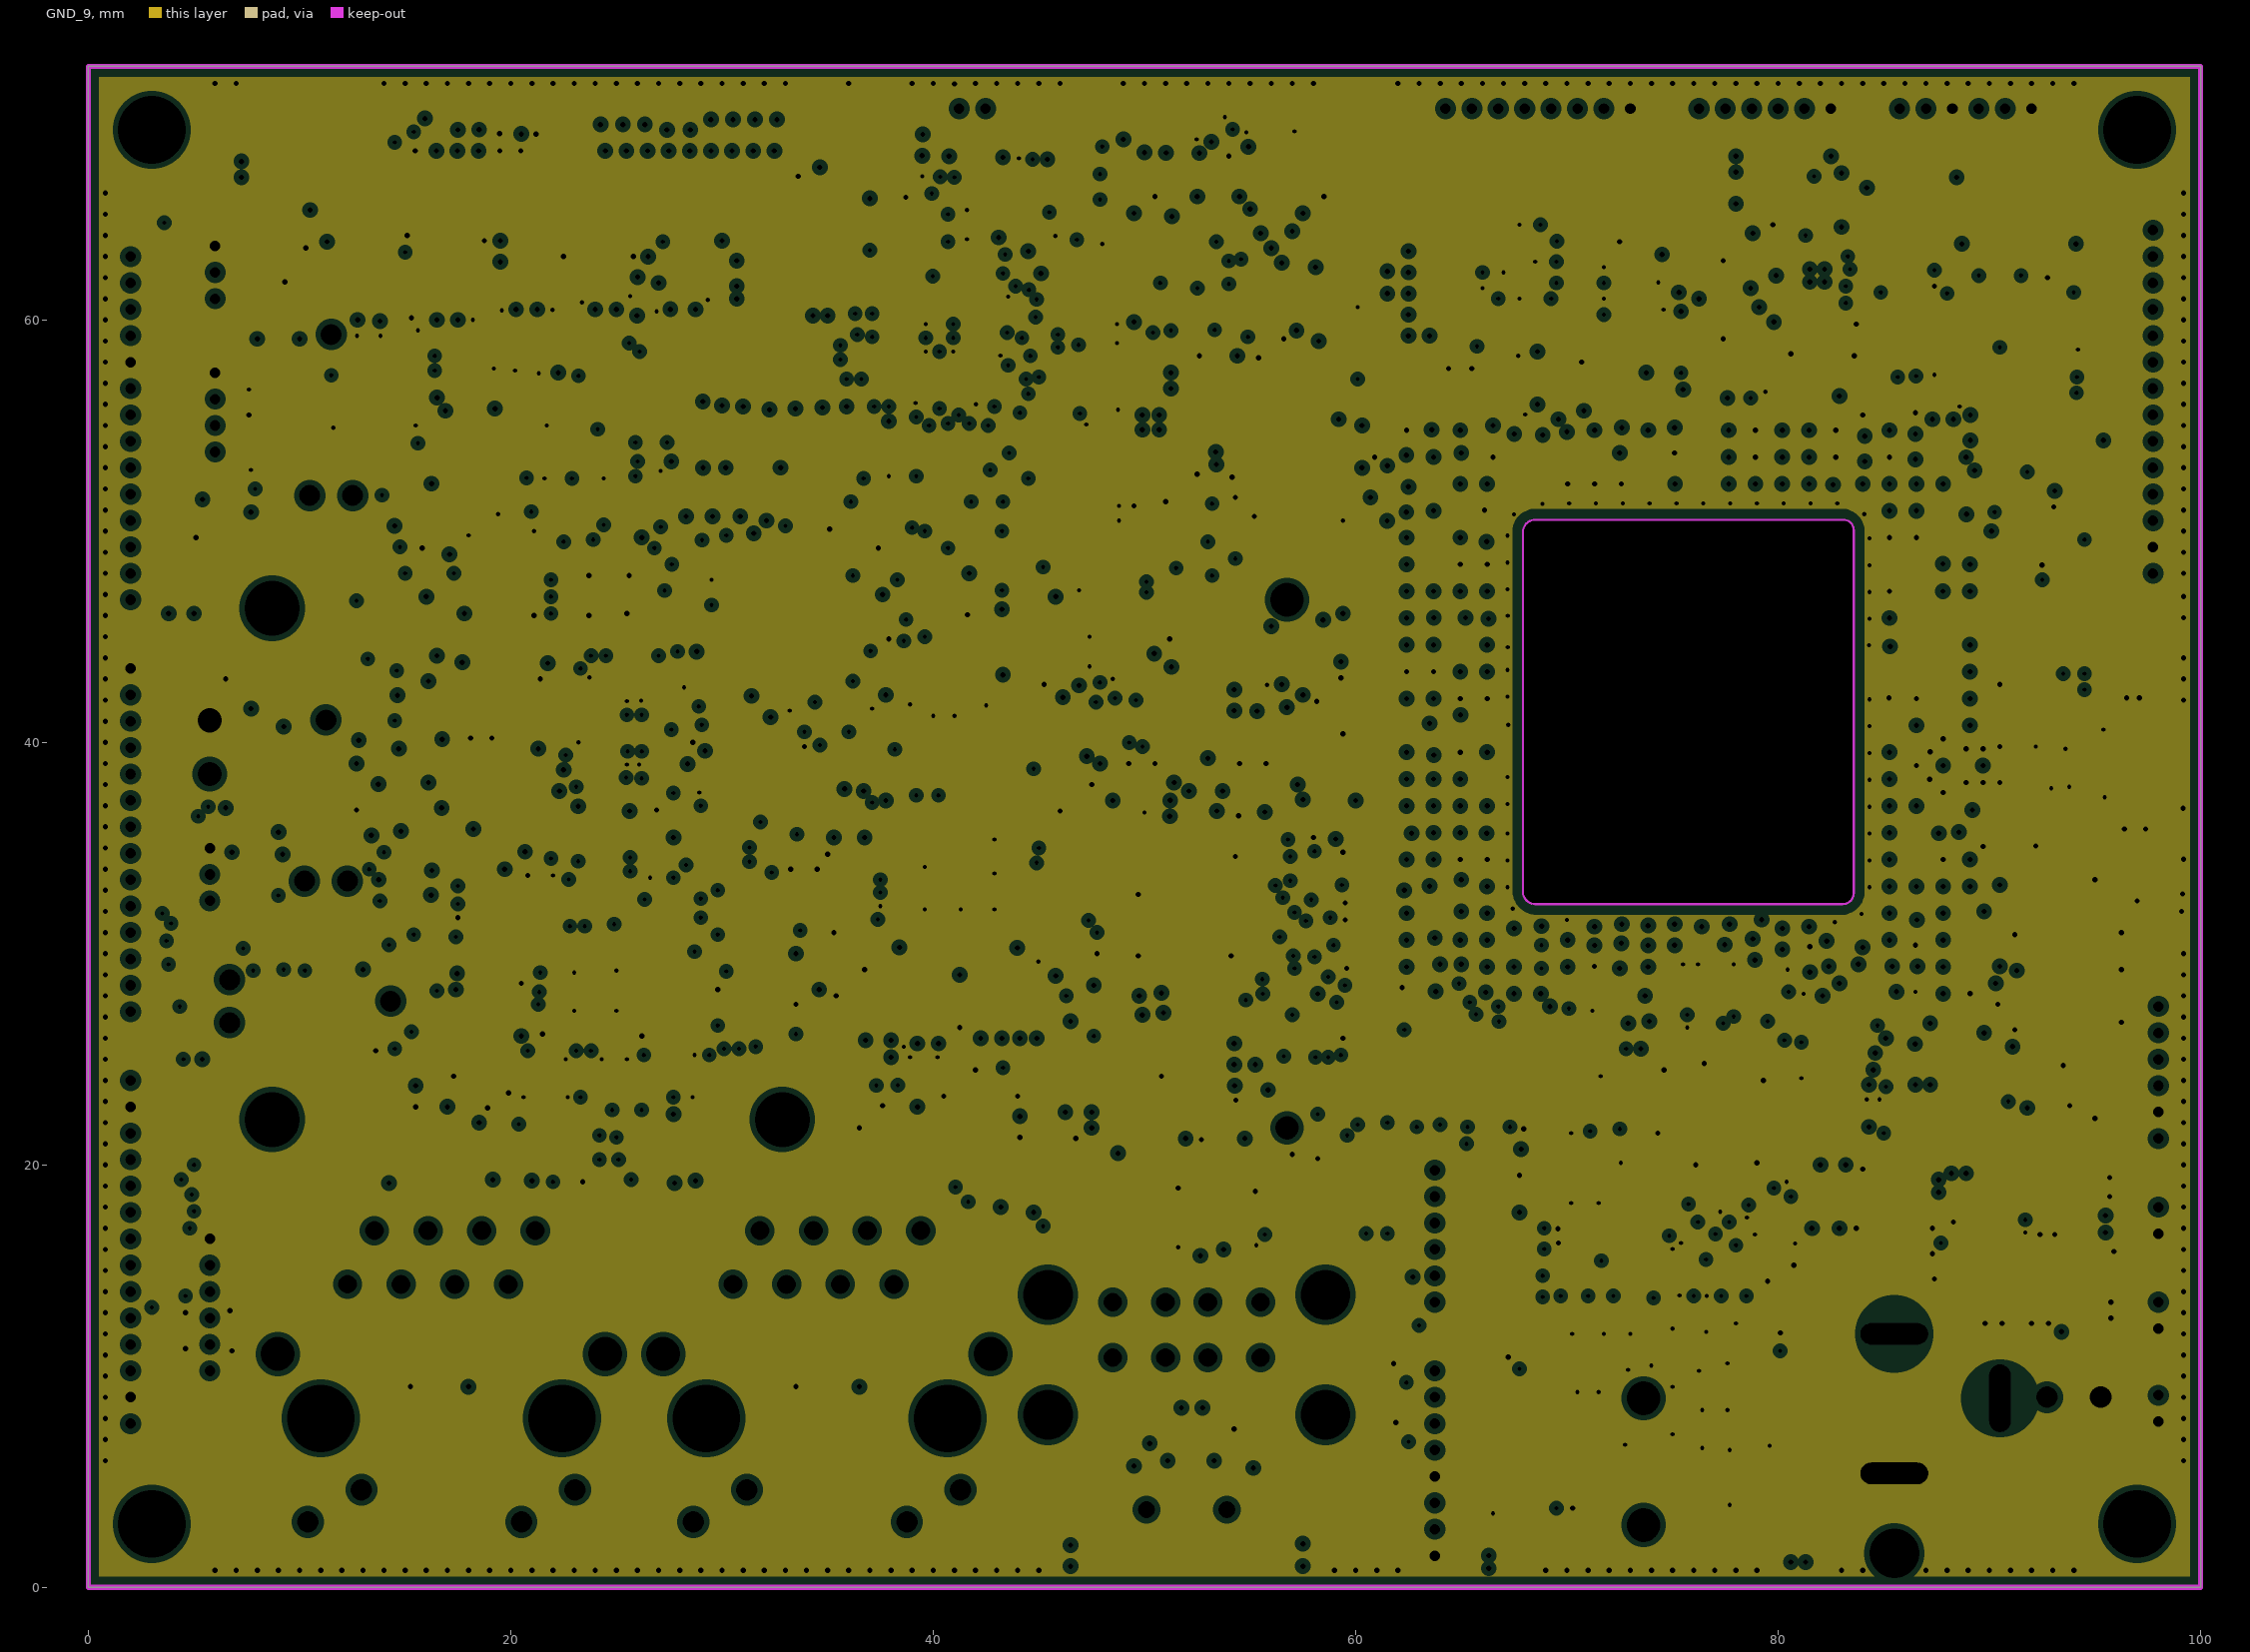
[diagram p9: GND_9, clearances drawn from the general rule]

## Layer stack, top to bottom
Top Solder: solder mask 0.0127, Dielectric, Dk 3.3
Top: signal copper 0.0432
Dielectric1: prepreg 0.076, IT-180A; 1086; Rc62%; (2GHz), Dk 3.9
GND_2: plane copper 0.0178, net GND
Dielectric2: core 0.127, IT-180A; 2-1080; (2GHz), Dk 3.7
Signal_3: signal copper 0.0178
Dielectric3: prepreg 0.127, IT-180A; 1067; Rc71%; (2GHz) x2, Dk 3.9
Signal_4: signal copper 0.0178
Dielectric 13: core 0.127, IT-180A; 2-1080; (2GHz), Dk 3.7
PWR_5: plane copper 0.0178, net (Multiple Nets)
Dielectric6: prepreg 0.457, IT-180A, Dk 3.9
GND_6: plane copper 0.0178, net (Multiple Nets)
Dielectric9: core 0.127, IT-180A; 2-1080; (2GHz), Dk 3.7
Signal_7: signal copper 0.0178
Dielectric10: prepreg 0.127, IT-180A; 1067; Rc71%; (2GHz) x2, Dk 3.9
Signal_8: signal copper 0.0178
Dielectric 12: core 0.127, IT-180A; 2-1080; (2GHz), Dk 3.7
GND_9: plane copper 0.0178, net GND
Dielectric11: prepreg 0.076, IT-180A; 1086; Rc62%; (2GHz), Dk 3.9
Bottom: signal copper 0.0432
Bottom Solder: solder mask 0.0127, Dielectric, Dk 3.3

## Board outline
0,0 0,72 100,72 100,0
cut-out: 67.92,49.96 cw(c68.5,49.96) 68.5,50.54 83.04,50.54 cw(c83.04,50) 83.58,50 83.58,32.92 cw(c83,32.92) 83,32.34 68.58,32.34 cw(c68.58,33) 67.92,33

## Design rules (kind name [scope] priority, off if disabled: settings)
AssemblyTestPointUsage [All] p1 off: valid=2
AssemblyTestpoint [All] p1 off: testpointundercomponent=TRUE minsize=1.016 maxsize=2.54 preferedsize=1.524 minholesize=0 maxholesize=1.016 preferedholesize=0.813 testpointgrid=0.025 usegrid=TRUE gridtolerance=0 allowsidetop=TRUE allowsidebottom=TRUE
Clearance Clearance_50ohm_RF [InNetClass('50ohm_RF') AND IsTrack vs InPoly] p1: gap=0.381 ignorepadtopadclearanceinfootprint=FALSE except(0: Arc-Hole Track-Hole SMDPad-Hole THPad-Hole Via-Hole Fill-Hole Poly-Hole Region-Hole Text-Hole)
Clearance Clearance_Diff-Pairs [(InDifferentialPairClass('All Differential Pairs')) AND IsTrack vs InPoly] p2: gap=0.381 ignorepadtopadclearanceinfootprint=FALSE except(0: Arc-Hole Track-Hole SMDPad-Hole THPad-Hole Via-Hole Fill-Hole Poly-Hole Region-Hole Text-Hole)
Clearance Clearance_U2_pad-to-track [(OnLayer('Top') AND InComponent('U2') AND IsPad) vs IsTrack] p3: gap=0.076 ignorepadtopadclearanceinfootprint=FALSE except(0: Arc-Hole Track-Hole SMDPad-Hole THPad-Hole Via-Hole Fill-Hole Poly-Hole Region-Hole Text-Hole)
Clearance Clearance_U25_pad-to-track [(OnLayer('Top') AND InComponent('U25') AND IsPad) vs IsTrack] p4: gap=0.102 ignorepadtopadclearanceinfootprint=FALSE except(0: Arc-Hole Track-Hole SMDPad-Hole THPad-Hole Via-Hole Fill-Hole Poly-Hole Region-Hole Text-Hole)
Clearance Clearance_BoardEdge [OnLayer('Keep-Out Layer')] p5: gap=0.4 ignorepadtopadclearanceinfootprint=FALSE except(0: Arc-Hole Track-Hole SMDPad-Hole THPad-Hole Via-Hole Fill-Hole Poly-Hole Region-Hole Text-Hole) // copper objects from board edge
Clearance "2mm thru hole to SMT" [IsPad and inSMTComponent and onBottom vs IsThruPin And InThruComponent  And Not ((ObjectKind = 'Pad') And (Layer = 'MultiLayer') And (Net = 'No Net') And (PadIsPlated = 'False'))] p6: gap=2 ignorepadtopadclearanceinfootprint=FALSE except(0: Arc-Hole Track-Hole SMDPad-Hole THPad-Hole Via-Hole Fill-Hole Poly-Hole Region-Hole Text-Hole)
Clearance Clearance_Poly [InPoly] p7: gap=0.2 ignorepadtopadclearanceinfootprint=FALSE except(0: Arc-Hole Track-Hole SMDPad-Hole THPad-Hole Via-Hole Fill-Hole Poly-Hole Region-Hole Text-Hole)
Clearance "Global Clearance" [All] p8: gap=0.127 ignorepadtopadclearanceinfootprint=FALSE except(0: Arc-Hole Track-Hole SMDPad-Hole THPad-Hole Via-Hole Fill-Hole Poly-Hole Region-Hole Text-Hole)
ComponentClearance [All] p1 off: gap=0.25 collisioncheckmode=3 verticalgap=0.25 showdistances=TRUE
DiffPairsRouting DiffPairsRouting_AUDIO [InDifferentialPairClass('AUD')] p1: maxlimit=0.15 minlimit=0.15 mostfreqgap=0.15 toplayer_minwidth=0.2 toplayer_maxwidth=0.2 toplayer_prefwidth=0.2 midlayer1_minwidth=0.2 midlayer1_maxwidth=0.2 midlayer1_prefwidth=0.2 midlayer2_minwidth=0.2 midlayer2_maxwidth=0.2 midlayer2_prefwidth=0.2 midlayer3_minwidth=0.2 midlayer3_maxwidth=0.2 midlayer3_prefwidth=0.2 midlayer4_minwidth=0.2 midlayer4_maxwidth=0.2 midlayer4_prefwidth=0.2 bottomlayer_minwidth=0.2 bottomlayer_maxwidth=0.2 bottomlayer_prefwidth=0.2 maxuncoupledlength=12.7
DiffPairsRouting "ICD Stackup Planner 100ohm" [InDifferentialPairClass('100_Ohms')] p2: maxlimit=0.203 minlimit=0.203 mostfreqgap=0.203 toplayer_minwidth=0.102 toplayer_maxwidth=0.102 toplayer_prefwidth=0.102 midlayer1_minwidth=0.127 midlayer1_maxwidth=0.127 midlayer1_prefwidth=0.127 midlayer2_minwidth=0.127 midlayer2_maxwidth=0.127 midlayer2_prefwidth=0.127 midlayer3_minwidth=0.127 midlayer3_maxwidth=0.127 midlayer3_prefwidth=0.127 midlayer4_minwidth=0.127 midlayer4_maxwidth=0.127 midlayer4_prefwidth=0.127 bottomlayer_minwidth=0.102 bottomlayer_maxwidth=0.102 bottomlayer_prefwidth=0.102 maxuncoupledlength=13.5
DiffPairsRouting "ICD Stackup Planner 90ohm" [InDifferentialPairClass('90_Ohms')] p3: maxlimit=0.203 minlimit=0.203 mostfreqgap=0.203 toplayer_minwidth=0.127 toplayer_maxwidth=0.127 toplayer_prefwidth=0.127 midlayer1_minwidth=0.165 midlayer1_maxwidth=0.165 midlayer1_prefwidth=0.165 midlayer2_minwidth=0.165 midlayer2_maxwidth=0.165 midlayer2_prefwidth=0.165 midlayer3_minwidth=0.165 midlayer3_maxwidth=0.165 midlayer3_prefwidth=0.165 midlayer4_minwidth=0.165 midlayer4_maxwidth=0.165 midlayer4_prefwidth=0.165 bottomlayer_minwidth=0.127 bottomlayer_maxwidth=0.127 bottomlayer_prefwidth=0.127 maxuncoupledlength=7.9
FabricationTestPointUsage TestPointUsage [All] p1 off: valid=2 allowmultiple=FALSE
FabricationTestpoint Testpoint [All] p1 off: side=3 testpointundercomponent=TRUE minsize=1.016 maxsize=2.54 preferedsize=1.524 minholesize=0 maxholesize=1.016 preferedholesize=0.813 testpointgrid=0.025 allowsidetop=TRUE allowsidebottom=TRUE usegrid=TRUE gridtolerance=0
FanoutControl Fanout_Small [(CompPinCount < 5)] p4: bgadir=Out bgaviamode=Closest fanoutstyle=Auto fanoutdirection=OutThenIn viagrid=0.025 // Fanout_Small (Default Rule)
HoleSize [All] p1: absolutevalues=TRUE maxlimit=3.3 minlimit=0.2 maxpercent=80.000 minpercent=20.000
HoleToHoleClearance [All] p1: gap=0.25 allowstackedmicrovias=TRUE
MatchedLengths MatchedLengths_SD2 [InxSignalClass('SD2')] p1: tolerance=0.1 checknetsindiffpair=FALSE checkdiffpairvsdiffpair=TRUE checkxsignals=TRUE checkothers=TRUE
MatchedLengths MatchedLengths_CSI-DAT [InxSignalClass('CSI_DAT')] p2: tolerance=0.1 checknetsindiffpair=FALSE checkdiffpairvsdiffpair=TRUE checkxsignals=TRUE checkothers=TRUE
MatchedLengths MatchedLengths_RGMII_R [InxSignalClass('RGMII_R')] p3: tolerance=0.1 checknetsindiffpair=FALSE checkdiffpairvsdiffpair=TRUE checkxsignals=TRUE checkothers=TRUE
MatchedLengths MatchedLengths_RGMII_T [InxSignalClass('RGMII_T')] p4: tolerance=0.1 checknetsindiffpair=FALSE checkdiffpairvsdiffpair=TRUE checkxsignals=TRUE checkothers=TRUE
MinimumAnnularRing [All] p1: minimumring=0.127
MinimumSolderMaskSliver [All] p1: minsoldermaskwidth=0.1
PlaneClearance "3V3 PlaneClearance" [(InNamedPolygon('Layer 7 3V3'))] p1: clearance=0.25
PlaneClearance [All] p2: clearance=0.25
PlaneConnect "Via_ Direct_Connect_to_Plane" [IsVia] p1: planeconnectstyle=Direct reliefexpansion=0.508 reliefentries=4 reliefconductorwidth=0.254 reliefairgap=0.254
PlaneConnect [All] p2: planeconnectstyle=Relief reliefexpansion=0.2 reliefentries=4 reliefconductorwidth=0.25 reliefairgap=0.2
PolygonConnect PolygonConnect_R1_R2 [(InNet('NetR1_2') OR InNet('NetR2_2'))] p1: connectstyle=Direct reliefconductorwidth=0.254 reliefentries=4 polygonreliefangle="90 Angle" airgapwidth=0.254
PolygonConnect PolygonConnect_U11 [InComponent('U11')] p2: connectstyle=Relief reliefconductorwidth=0.127 reliefentries=4 polygonreliefangle="90 Angle" airgapwidth=0.254
PolygonConnect PolygonConnect_J18 [InComponent('J18')] p3: connectstyle=Direct reliefconductorwidth=0.254 reliefentries=4 polygonreliefangle="90 Angle" airgapwidth=0.254
PolygonConnect PolygonConnect_NETFIL1_1_L01_P131 [InNet('NetFIL1_1')] p4: connectstyle=Direct reliefconductorwidth=0.254 reliefentries=4 polygonreliefangle="90 Angle" airgapwidth=0.254
PolygonConnect Polysolid [All vs IsnamedPolygon('Polysolid','Polysolid_L6')] p5: connectstyle=Direct reliefconductorwidth=0.254 reliefentries=4 polygonreliefangle="90 Angle" airgapwidth=0.254
PolygonConnect "Polygon To Via" [IsVia] p6: connectstyle=Direct reliefconductorwidth=0.254 reliefentries=4 polygonreliefangle="90 Angle" airgapwidth=0.254
PolygonConnect [All] p7: connectstyle=Relief reliefconductorwidth=0.25 reliefentries=4 polygonreliefangle="90 Angle" airgapwidth=0.2
RoomDefinition U2_break-out [OnLayer('Top')] p1 off: confinementstyle=ConfineOut formatcopy=TRUE lockcomponents=FALSE outline 64,59 71.5,59 71.5,66.5 64,66.5
RoutingCorners [All] p1: cornerstyle=45-Degree minsetback=2 maxsetback=2
RoutingLayers RoutingLayers_DSI_CLK0 [InNet('DSI_CLK0_N') or InNet('DSI_CLK0_P')] p1: top layer_v5=TRUE mid layer 1_v5=TRUE mid layer 2_v5=TRUE mid layer 3_v5=TRUE mid layer 4_v5=TRUE bottom layer_v5=TRUE
RoutingLayers RoutingLayers_Power [InNetClass('Power')] p2: top layer_v5=TRUE mid layer 1_v5=TRUE mid layer 2_v5=TRUE mid layer 3_v5=TRUE mid layer 4_v5=TRUE bottom layer_v5=TRUE
RoutingLayers RoutingLayers_50_Ohms [InNetClass('50_Ohm')] p3: top layer_v5=TRUE mid layer 1_v5=TRUE mid layer 2_v5=TRUE mid layer 3_v5=TRUE mid layer 4_v5=TRUE bottom layer_v5=TRUE
RoutingLayers RoutingLayers_GND [InNetClass('GND')] p4: top layer_v5=TRUE mid layer 1_v5=TRUE mid layer 2_v5=TRUE mid layer 3_v5=TRUE mid layer 4_v5=TRUE bottom layer_v5=TRUE
RoutingLayers "RoutingLayers_100_Ohm Diff Pairs" [InDifferentialPairClass ('100_Ohms')] p5: top layer_v5=TRUE mid layer 1_v5=TRUE mid layer 2_v5=TRUE mid layer 3_v5=TRUE mid layer 4_v5=TRUE bottom layer_v5=TRUE
RoutingLayers "RoutingLayers_90_Ohm Diff Pairs" [InDifferentialPairClass ('90_Ohms')] p6: top layer_v5=TRUE mid layer 1_v5=TRUE mid layer 2_v5=TRUE mid layer 3_v5=TRUE mid layer 4_v5=TRUE bottom layer_v5=TRUE
RoutingLayers "RoutingLayers_85_Ohm Diff Pairs" [InDifferentialPairClass ('85_Ohms')] p7: top layer_v5=TRUE mid layer 1_v5=TRUE mid layer 2_v5=TRUE mid layer 3_v5=TRUE mid layer 4_v5=TRUE bottom layer_v5=TRUE
RoutingLayers [All] p8: top layer_v5=TRUE mid layer 1_v5=TRUE mid layer 2_v5=TRUE mid layer 3_v5=TRUE mid layer 4_v5=TRUE bottom layer_v5=TRUE
RoutingVias "ICD Stackup Planner PTH Via 1" [All] p1: holewidth=0.25 width=0.56 viastyle="Through Hole" minholewidth=0.2 minwidth=0.457 maxholewidth=1 maxwidth=1.5
SMDNeckDown [All] p1: percent=100.000
SilkToBoardRegionClearance [All] p1 off:
SilkToSilkClearance [All] p1 off: silktosilkclearance=0.125
SilkToSolderMaskClearance SilkscreenOverComponentPads [IsPad] p1 off: minsilkscreentomaskgap=0.125 clearancetoexposedcopper=TRUE
SolderMaskExpansion SolderMaskExpansion_U2_U25 [(InComponent('U2') OR InComponent('U25'))] p1: expansion=0
SolderMaskExpansion [All] p2: expansion=0.05
Width Width_U2 [WithinRoom('U2_break-out') AND OnLayer('Top')] p1: maxlimit=0.254 minlimit=0.076 preferedwidth=0.1 midlayer1_minwidth=0.1 midlayer2_minwidth=0.1 bottomlayer_minwidth=0.1 minimp=50.000000 maximp=50.000000 favimp=50.000000
Width "Width 50_Ohms" [InNetClass('50_Ohms')] p2: maxlimit=0.127 minlimit=0.119 preferedwidth=0.127 toplayer_maxwidth=0.119 toplayer_prefwidth=0.119 midlayer1_minwidth=0.127 midlayer2_minwidth=0.127 midlayer3_minwidth=0.127 midlayer4_minwidth=0.127 bottomlayer_maxwidth=0.119 bottomlayer_prefwidth=0.119 minimp=50.000000 maximp=50.000000 favimp=50.000000
Width "Width Power" [InNetClass('Power')] p3: maxlimit=1 minlimit=0.125 preferedwidth=0.25
Width [All] p4: maxlimit=0.5 minlimit=0.1 preferedwidth=0.125
13 further rules are at their usual default settings.

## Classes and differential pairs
differential pair class AUD: SPKL SPKR
net class UART: UART2_CTS_N/CAN2_TX UART2_RTS_N/CAN2_RX UART2_RX UART2_TX UART3_CTS_N/CAN1_TX UART3_RTS_N/CAN1_RX UART3_RX UART3_TX UART5_RX UART5_TX UART_PWR/IO18
net class DISP: DISP_5V_PWR/IO29 LCD_CLK LCD_DATA0 LCD_DATA0_PROT LCD_DATA1 LCD_DATA1_PROT LCD_DATA2 LCD_DATA2_PROT LCD_DATA3 LCD_DATA3_PROT LCD_DATA4 LCD_DATA4_PROT LCD_DATA5 LCD_DATA5_PROT LCD_DATA6 LCD_DATA6_PROT LCD_DATA7 LCD_DATA7_PROT LCD_DATA8 LCD_DATA9 LCD_DATA10 LCD_DATA11 LCD_DATA12 LCD_DATA13 LCD_DATA14 LCD_DATA15 LCD_DATA16 LCD_DATA17 LCD_DATA19 LCD_DATA20/SPI1_CLK LCD_DATA21/SPI1_SS0 LCD_DATA22/SPI1_MOSI LCD_DATA23/SPI1_MISO LCD_DRDY LCD_HSYNC LCD_I2C_SCL LCD_I2C_SDA LCD_IRQ_N LCD_RESET LCD_VSYNC
net class ENET: ENET1_INT# ENET1_RX_DATA0 ENET1_RX_DATA1 ENET1_RX_EN ENET1_RX_ER ENET1_TX_CLK ENET1_TX_DATA0 ENET1_TX_DATA1 ENET1_TX_EN ENET2_INT# ENET2_RX_DATA0 ENET2_RX_DATA1 ENET2_RX_EN ENET2_RX_ER ENET2_TX_CLK ENET2_TX_DATA0 ENET2_TX_DATA1 ENET2_TX_EN ENET_MDC ENET_MDIO ENET_PWR/IO26
net class 5A: NetFIL1_1 VIN VIN_PROT
net class 3A: NetC56_2
net class DIFF90: OTGD_N OTGD_P USB_OTG_D_N USB_OTG_D_P USBH1_D_N USBH1_D_P USBH2_D_N USBH2_D_P USBH3_D_N USBH3_D_P USBH4_D_N USBH4_D_P USBH_D_N USBH_D_P XBEE_USB_N XBEE_USB_P
net class 50ohm_RF: NetC61_2 NetC80_2
net class 1.25A: 3V3
component class "12 - Bootstrap": C151 C152 C153 J10 R17 R24 R25 R28 R29 R100 R112 R113 R147 R153 R156 R166 R213 R214 R215 R216 R217 R218 R219 R220 R221 R222 R233 R234 R235 R236 R237 R238 R239 U30 U31
net class Clocks: CSI_MCLK CSI_PIXCLK LCD_CLK NetJ7_5 PCIE_UIM_CLK
differential pair class 85_Ohms: CLK1 PCIE_RX PCIE_TX PCIECLK PCIERX PCIETX
differential pair class 90_Ohms: OTGD USB_OTG_D USBH1_D USBH2_D USBH3_D USBH4_D USBH_D XBEE_USB
differential pair class 100_Ohms: ETH1_RX ETH1_TX ETH2_RX ETH2_TX LVDS0_CLK LVDS0_TX0 LVDS0_TX1 LVDS0_TX2 LVDS0_TX3
component class "11 - Expansion Connectors, User LEDs, NTAG": C144 C145 C146 C147 D4 D14 J26 J27 J28 J29 J30 J32 J34 J36 R3 R4 R80 R89 R117 R118 R119 R122 R181 R201 R202 R203 R204 R205 R227 R228 R229 R230 R253 R256 U28
component class "10 - CAN, I2C, XBee": C99 C100 C101 C114 D11 J23 J24 J25 L28 L29 Q5 R40 R77 R84 R95 R96 R101 R102 R103 R104 R105 R106 R107 R108 R109 R110 R111 R114 R115 R116 R123 R129 R130 R133 R134 R135 R136 R145 R146 R187 R188 R199 R200 R263 R264 R267 R281 TP9 TP10 TP11 TP12 TP13 TP14 TP15 U18 U19
component class "09 - Audio": C87 C88 C89 C90 C91 C92 C93 C94 C95 C96 C97 C98 C102 C103 C118 C129 C131 C132 C133 C134 C135 C136 C137 C138 C139 C140 C141 C142 C143 C149 J22 J33 L19 L20 L21 L22 L23 L24 NT1 Q4 R91 R92 R93 R94 R128 R131 R132 R189 R190 R191 R192 R193 R194 R195 R196 R197 R198 R206 R255 R276 R277 R278 U6 U17 U22
component class "08 - Displays and camera": C60 C81 C82 C83 C84 C85 C158 J17 J21 J31 L5 L18 L30 L31 L32 L33 L34 Q11 R41 R78 R168 R169 R170 R171 R172 R173 R174 R175 R176 R177 R178 R207 R208 R209 R210 R211 R248 R249 R250 R251 R252 R258 R259 R266 U25 U35
component class "07 - USB OTG, USB HUB, USB Host": C62 C63 C64 C65 C66 C67 C68 C69 C70 C71 C72 C73 C74 C75 C76 C77 C78 C79 C154 C155 D10 J15 J16 L6 L7 L8 L9 L10 L11 L12 L13 L14 L15 L16 L17 Q2 Q10 R15 R16 R18 R19 R64 R65 R66 R67 R68 R69 R70 R71 R72 R73 R74 R75 R82 R240 R242 U12 U13 U14 U15 U20 U21 U32 X2
component class "06 - Ethernet": C15 C16 C17 C18 C19 C26 C28 C29 C30 C31 C32 C33 C40 C41 C42 C43 C44 C45 C46 C47 C48 C49 C50 C51 C52 C53 C54 J6 J8 L2 L3 Q7 R7 R9 R10 R26 R27 R43 R44 R45 R46 R47 R48 R49 R50 R51 R52 R53 R54 R55 R56 R57 R58 R59 R60 R61 R62 R63 R76 R79 R85 R86 R87 R88 R90 R124 R154 R157 R158 R159 R160 R161 R162 R163 R164 R165 U8 U16 U24
component class "05 - JTAG, SWD, Console, UART, IO expander": C20 C21 C23 C25 C27 C104 C105 C106 C120 C122 C124 CAD1 CAD2 CAD3 D6 D7 J9 J11 J37 R36 R37 R81 R121 R125 R127 R149 R150 R151 R152 R155 R232 R247 R254 R257 R262 R265 R268 R269 R280 R282 U9 U27
component class "03 - Power, boot strap, reset": C1 C2 C3 C8 C9 C10 C11 C55 C56 C57 C58 C59 C86 C121 C130 D1 D2 D13 FIL1 J1 J2 J3 J4 J5 J35 Q1 Q9 R6 R8 R11 R12 R13 R14 R21 R22 R83 R97 R98 R99 R120 R126 R148 R167 R179 R180 R182 R183 R184 R212 R224 R225 R226 R261 R279 SW1 SW2 U1 U3 U5 U7 U26
component class "02 - CCIMX6UL Module": C61 C80 C150 D3 D12 J13 J18 J19 J20 L4 R1 R2 R5 R20 R23 R38 R39 R42 R231 R260 R270 R271 R272 R273 R274 R275 R283 SW4 TP1 TP2 TP3 TP4 TP5 TP8 TP16 U10 U11 U36
component class "04 - MicroSD, eMMC, Mini PCIe, microSIM": C4 C5 C6 C7 C12 C13 C14 C22 C24 C34 C35 C36 C37 C38 C39 C107 C108 C109 C110 C111 C112 C113 C115 C116 C117 C119 C125 C126 C127 C128 C156 C157 J7 J12 J14 L1 Q6 R30 R31 R32 R33 R34 R35 R137 R138 R139 R140 R141 R142 R143 R144 R185 R186 R223 R241 R243 R244 R245 R246 U2 U4 U23 U33 U34
net class Power: 1V8_CODEC 3V3 3V3_CODEC 3V3_EMMC 3V3_ETH 3V3_INT 3V3_USB 5V 5V_DISPLAY AVDD1 AVDD2 LDO4_1V8 NetC56_2 NetC130_2 NetCAD1_5 NetCAD2_5 NetCAD3_5 NetD13_3 NetR1_2 NTAG_VCC PCIE_VCC VCC_LICELL VCC_MCA VDDCR1 VDDCR2 VIN VIN_PROT
net class 50_Ohms: AUD_I2C_SCL AUD_I2C_SDA AUD_INT# AUD_PWR/IO28 BT_EN BT_LED BT_UART1_CTS BT_UART1_RTS# BT_UART1_RX BT_UART1_TX BT_WAKEUP_HOST BT_WAKEUP_SLAVE CAN_STBY/IO34 CSI_DATA02 CSI_DATA03 CSI_DATA04 CSI_DATA05 CSI_DATA06 CSI_DATA07 CSI_DATA08 CSI_DATA09 CSI_GPIO/IO31 CSI_HSYNC CSI_I2C_SCL CSI_I2C_SDA CSI_MCLK CSI_PIXCLK CSI_PWDN/IO22 CSI_VSYNC EMMC/SD# EMMC_CLK EMMC_CMD EMMC_PWR/IO8 ENET1_INT# ENET1_RX_DATA0 ENET1_RX_DATA1 ENET1_RX_EN ENET1_RX_ER ENET1_TX_CLK ENET1_TX_DATA0 ENET1_TX_DATA1 ENET1_TX_EN ENET2_INT# ENET2_RX_DATA0 ENET2_RX_DATA1 ENET2_RX_EN ENET2_RX_ER ENET2_TX_CLK ENET2_TX_DATA0 ENET2_TX_DATA1 ENET2_TX_EN ENET_MDC ENET_MDIO ENET_PWR/IO26 EXP_GPIO_1 EXP_GPIO_2 EXP_GPIO_3 EXP_I2C_GPIO/IO32 EXP_I2C_IRQ_N EXP_I2C_SCL EXP_I2C_SDA I2C1_SCL I2C1_SDA INTERNAL_I2C1_SCL INTERNAL_I2C1_SDA IOEXP_3 IOEXP_4 IOEXP_5 IOEXP_6 IOEXP_37 IOEXP_I2C0_SCL IOEXP_I2C0_SDA IOEXP_RESET_N IOEXP_SWD_CLK/LVDS_FLIP IOEXP_SWD_DIO/LVDS_RF IOEXP_UART2_RX IOEXP_UART2_TX JTAG_MOD JTAG_TCK/SAI2_RX_DATA JTAG_TDI/SAI2_TX_BCLK JTAG_TDO/SAI2_TX_SYNC JTAG_TMS/SAI2_MCLK JTAG_TRST_N/SAI2_TX_DATA LCD_CLK LCD_DATA0 LCD_DATA0_PROT LCD_DATA1 LCD_DATA1_PROT LCD_DATA2 LCD_DATA2_PROT LCD_DATA3 LCD_DATA3_PROT LCD_DATA4 LCD_DATA4_PROT LCD_DATA5 LCD_DATA5_PROT LCD_DATA6 LCD_DATA6_PROT LCD_DATA7 LCD_DATA7_PROT LCD_DATA8 LCD_DATA9 LCD_DATA10 LCD_DATA11 LCD_DATA12 LCD_DATA13 LCD_DATA14 LCD_DATA15 LCD_DATA16 LCD_DATA17 LCD_DATA19 LCD_DATA20/SPI1_CLK LCD_DATA21/SPI1_SS0 LCD_DATA22/SPI1_MOSI LCD_DATA23/SPI1_MISO LCD_DRDY LCD_HSYNC LCD_I2C_SCL LCD_I2C_SDA LCD_IRQ_N LCD_RESET LCD_VSYNC LDOG LINE_IN_B_L LINE_IN_B_R LTE_PRI LTE_SYNC LVDS_6B8B LVDS_FLIP LVDS_MAP LVDS_PD#/IO30 LVDS_RF LVDS_RS MCA_CLKOUT32K MCA_IO1 MCA_IO3 MCA_RESET_N MCA_SWD_CLK/PWR_IO NTAG/IOEXP_I2C1_SCL NTAG/IOEXP_I2C1_SDA NTAG_FD NTAG_FD/IO35 NTAG_I2C_SCL NTAG_I2C_SDA ON/OFF PCIE_DIS_N/IO12 PCIE_I2C_SCL PCIE_I2C_SDA PCIE_UIM_CLK PCIE_UIM_DATA PCIE_UIM_PWR PCIE_UIM_RST PCIE_UIM_VPP PCIE_WAKE_N/IO38 PCM_CLK PCM_IN PCM_OUT PCM_SYNC POR_B RF1_INT/NEXT RF_KILL RF_KILL_HW# RF_KILL_SW#/IO2 RS232_3_CTS_N RS232_3_RTS_N RS232_3_RX RS232_3_TX RS232_IOEXP_2_RX RS232_IOEXP_2_TX SD_CLK SD_CMD SPI1_IRQ_N UART2_CTS_N/CAN2_TX UART2_RTS_N/CAN2_RX UART2_RX UART2_TX UART3_CTS_N/CAN1_TX UART3_RTS_N/CAN1_RX UART3_RX UART3_TX UART5_RX UART5_TX UART_PWR/IO18 WL_EN WLAN_SD1_CLK WLAN_SD1_CMD WLAN_SD1_D4/GPIO4 WLAN_SD1_D5/GPIO3 WLAN_SD1_D6/GPIO2 WLAN_SD1_D7/GPIO1 WLAN_SD1_DATA0 WLAN_SD1_DATA1 WLAN_SD1_DATA2 WLAN_SD1_DATA3 WLAN_SDIO_INT_L XBEE_ASSOC XBEE_IDENT/IO33 XBEE_ON/SLP_N/IO11 XBEE_RSTN/IO7 XBEE_SLP_RQ/IO9
component class "14 - History, Mechanicals": FIDUCIAL1 FIDUCIAL2 FIDUCIAL3 FIDUCIAL4 FIDUCIAL5 FIDUCIAL6 FIDUCIAL7 FIDUCIAL8 FIDUCIAL9 FIDUCIAL10 FIDUCIAL11 FIDUCIAL12 H1 H2 H3 H4 LBL1
net class "micro SIM": PCIE_UIM_CLK PCIE_UIM_DATA PCIE_UIM_PWR PCIE_UIM_RST PCIE_UIM_VPP
net class CSI0: CSI_DATA02 CSI_DATA03 CSI_DATA04 CSI_DATA05 CSI_DATA06 CSI_DATA07 CSI_DATA08 CSI_DATA09 CSI_GPIO/IO31 CSI_HSYNC CSI_I2C_SCL CSI_I2C_SDA CSI_MCLK CSI_PIXCLK CSI_PWDN/IO22 CSI_VSYNC
differential pair class Audio: MIC SPKL SPKR
differential pair ETH1_TX: +ETH1_TX_P -ETH1_TX_N
differential pair ETH1_RX: +ETH1_RX_P -ETH1_RX_N
differential pair ETH2_TX: +ETH2_TX_P -ETH2_TX_N
differential pair ETH2_RX: +ETH2_RX_P -ETH2_RX_N
differential pair USBH2_D: +USBH2_D_P -USBH2_D_N
differential pair USBH3_D: +USBH3_D_P -USBH3_D_N
differential pair USBH4_D: +USBH4_D_P -USBH4_D_N
differential pair OTGD: +OTGD_P -OTGD_N
differential pair USBH_D: +USBH_D_P -USBH_D_N
differential pair USBH1_D: +USBH1_D_P -USBH1_D_N
differential pair USB_OTG_D: +USB_OTG_D_P -USB_OTG_D_N
differential pair LVDS0_TX3: +LVDS0_TX3_P -LVDS0_TX3_N
differential pair LVDS0_TX2: +LVDS0_TX2_P -LVDS0_TX2_N
differential pair LVDS0_TX1: +LVDS0_TX1_P -LVDS0_TX1_N
differential pair LVDS0_TX0: +LVDS0_TX0_P -LVDS0_TX0_N
differential pair LVDS0_CLK: +LVDS0_CLK_P -LVDS0_CLK_N
differential pair XBEE_USB: +XBEE_USB_P -XBEE_USB_N
differential pair SPKL: +SPKL_P -SPKL_N
differential pair SPKR: +SPKR_P -SPKR_N
differential pair MIC: +MIC_P -MIC_N

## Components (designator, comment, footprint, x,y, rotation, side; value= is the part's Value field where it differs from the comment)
C1 "100uF" CAPMP3216X120N 91.4,18.7 r0 top
C2 "10uF" CAPC1005X55N#1 93.364,20.542 r180 top
C3 "1.0UF" CAPC1005X55N#1 88.3,18.5 r90 top
C4 "100nF" CAPC1005X55N#2 68.25,65.25 r0 bottom
C5 "100nF" CAPC1005X55N#2 68.5,61.5 r270 bottom
C6 "100nF" CAPC1005X55N#2 72.5,62.4 r270 bottom
C7 "4.7µF" CAPC1005X55AL 72.5,60.6 r270 bottom
C8 "22µF" CAPC1608X90N#1 93.1,25.65 r0 bottom
C9 "100uF" CAPMP3216X120N 93.1,27.7 r180 bottom
C10 "100nF" CAPC1005X55N#1 95,23.4 r90 bottom
C11 "10uF" CAPC1005X55N#1 93.2,22.2 r180 bottom
C12 "10uF" CAPC1005X55N#1 73.5,14.98 r270 top
C13 "100nF" CAPC1005X55N#1 74.75,14.98 r270 top
C14 "100nF" CAPC1005X55N#1 63,26 r90 bottom
C15 "4.7uF" CAPC2013X135N 18.75,24.5 r90 bottom
C16 "100nF" CAPC1005X55N#1 27.5,25.2 r180 bottom
C17 "100nF" CAPC1005X55N#1 20.5,27.25 r90 bottom
C18 "1.0uF" CAPC1005X55N#1 28.5,28.25 r180 bottom
C19 "1.0uF" CAPC1005X55N#1 28.4,47.7 r180 bottom
C20 "100nF" CAPC1005X55N#1 30.225,41.25 r90 bottom
C21 "100nF" CAPC1005X55N#1 32.8,42 r180 top
C22 "100nF" CAPC1005X55N#1 50.5,33.25 r90 bottom
C23 "100nF" CAPC1005X55N#1 22.8,42.4 r90 top
C24 "1nF" CAPC1005X55N#2 72.6,58.5 r90 bottom
C25 "100nF" CAPC1005X55N#1 22.8,40.6 r90 top
C26 "1nF" CAPC1005X55N#2 19.25,33.25 r0 bottom
C27 "100nF" CAPC1005X55N#1 32.408,40.1 r180 top
C28 "100nF" CAPC1005X55N#1 24.5,32.5 r90 bottom
C29 "22nF" CAPC1608X90N#2 37.541,20.998 r270 top
C30 "100nF" CAPC1005X55N#1 24.3,24.2 r180 bottom
C31 "100nF" CAPC1005X55N#1 26.7,24.2 r0 bottom
C32 "100nF" CAPC1005X55N#1 23.1,21.4 r180 bottom
C33 "100nF" CAPC1005X55N#1 26.2,21.4 r0 bottom
C34 "100uF" CAPMP3216X120N 48.5,45.5 r270 bottom
C35 "100uF" CAPMP3216X120N 48.75,23.5 r90 bottom
C36 "100uF" CAPMP3216X120N 64.742,25.2 r270 bottom
C37 "100nF" CAPC1005X55N#1 50.25,45.5 r90 bottom
C38 "100nF" CAPC1005X55N#1 50.75,23 r270 bottom
C39 "100nF" CAPC1005X55N#1 63,28.25 r270 bottom
C40 "4.7uF" CAPC2013X135N 18.75,31 r270 bottom
C41 "1.0uF" CAPC1005X55N#1 20.5,31.9 r270 bottom
C42 "470pF" CAPC1005X55N#1 20.5,30 r90 bottom
C43 "4.7uF" CAPC2013X135N 19.139,42.157 r90 bottom
C44 "100nF" CAPC1005X55N#1 28.25,43.5 r180 bottom
C45 "100nF" CAPC1005X55N#1 21.1,44.9 r90 bottom
C46 "100nF" CAPC1005X55N#1 24.389,51.407 r90 bottom
C47 "22nF" CAPC1608X90N#2 15.5,21 r270 bottom
C48 "100nF" CAPC1005X55N#1 24.25,42.5 r180 bottom
C49 "100nF" CAPC1005X55N#1 27.25,42.5 r0 bottom
C50 "100nF" CAPC1005X55N#1 24.2,39.425 r180 bottom
C51 "100nF" CAPC1005X55N#1 27.2,39.4 r0 bottom
C52 "4.7uF" CAPC2013X135N 19.139,48.907 r270 bottom
C53 "1.0uF" CAPC1005X55N#1 21.1,49.1 r270 bottom
C54 "470pF" CAPC1005X55N#1 21.1,47.1 r90 bottom
C55 "470pF" CAPC1005X55N#1 92.4,17.9 r90 bottom
C56 "47uF" CAPC2013X145N 92.4,14.4 r90 bottom
C57 "47uF" CAPC2013X145N 90.2,14.4 r90 bottom
C58 "4.7uF" CAPC2013X135N 94.5,14.4 r90 bottom
C59 "100nF" CAPC1005X55N#1 94.3,16.5 r0 bottom
C60 "100nF" CAPC1005X55N#1 40.3,60.6 r180 bottom
C61 "0.3pF" CAPC0603X33AL 93,38.625 r90 top
C62 "1.0UF" CAPC1005X55N#1 33.475,28.925 r90 top
C63 "33pF" CAPC1005X55N#1 46,35.5 r90 bottom
C64 "33pF" CAPC1005X55N#1 48.25,32.25 r0 bottom
C65 "1.0UF" CAPC1005X55N#1 31.85,30.3 r270 bottom
C66 "100nF" CAPC1005X55N#1 33.2,32.46 r270 top
C67 "10uF" CAPC1005X55N#1 34.45,32.46 r270 top
C68 "100nF" CAPC1005X55N#1 30.6,30.3 r90 bottom
C69 "10uF" CAPC1005X55N#1 35,29.25 r180 bottom
C70 "100nF" CAPC1005X55N#1 35,30.5 r180 bottom
C71 "10uF" CAPC1005X55N#1 45.3,20.8 r0 top
C72 "10uF" CAPC1005X55N#1 46.2,38 r180 bottom
C73 "100nF" CAPC1005X55N#1 36.25,34.75 r0 bottom
C74 "100nF" CAPC1005X55N#1 36.25,31.75 r0 bottom
C75 "100nF" CAPC1005X55N#1 41.25,27.75 r90 bottom
C76 "100nF" CAPC1005X55N#1 46.2,29.6 r180 bottom
C77 "100nF" CAPC1005X55N#1 38.75,40 r270 bottom
C78 "100nF" CAPC1005X55N#1 36.25,33.5 r0 bottom
C79 "100nF" CAPC1005X55N#1 46.2,31.8 r180 bottom
C80 "0.1pF" CAPC0603X33AL 91.25,38.65 r90 top
C81 "100nF" CAPC1005X55N#1 38.675,60.125 r90 bottom
C82 "100nF" CAPC1005X55N#1 38.675,58.175 r270 bottom
C83 "100nF" CAPC1005X55N#1 41.925,59.725 r90 bottom
C84 "100nF" CAPC1005X55N#1 40.4,57.7 r0 bottom
C85 "100nF" CAPC1005X55N#1 41.925,57.775 r270 bottom
C86 "1.0uF" CAPC1005X55L 93.63,58.337 r270 top
C87 "100nF" CAPC1005X55N#1 83.1,23.1 r0 bottom
C88 "1.0UF" CAPC1005X55N#1 73.3,17.5 r270 bottom
C89 "100nF" CAPC1005X55N#1 81.1,27 r90 bottom
C90 "1.0uF" CAPC1005X55N#1 70.9,18.6 r90 bottom
C91 "10uF" CAPC2013X135N 71.6,17.2 r0 top
C92 "1.0UF" CAPC1005X55N#1 75,17.3 r0 bottom
C93 "1.0UF" CAPC1005X55N#1 78.5,28.5 r90 bottom
C94 "1.0UF" CAPC1005X55N#1 79.7,28.5 r90 bottom
C95 "1.0uF" CAPC1005X55N#1 72.2,18.7 r90 bottom
C96 "2.2µF" CAPC1005X55N#2 76.2,28.4 r90 bottom
C97 "1.0uF" CAPC1005X55N#1 77.3,28.5 r270 bottom
C98 "10uF" CAPC2013X135N 82.5,18.5 r180 top
C99 "100nF" CAPC1005X55N#1 86.6,58.2 r180 bottom
C100 "100nF" CAPC1005X55N#1 92.15,58.1 r180 bottom
C101 "100nF" CAPC1005X55N#1 15.75,50.5 r90 top
C102 "1.0uF" CAPC1005X55N#2 80.6,17.4 r270 bottom
C103 "1.0uF" CAPC1005X55N#2 79.6,17.4 r270 bottom
C104 "100nF" CAPC1005X55N#2 54.5,37.75 r270 top
C105 "100nF" CAPC1005X55N#2 47,30.192 r90 top
C106 "1.0uF" CAPC1005X55AL 55.75,37.75 r270 top
C107 "100nF" CAPC1005X55N#2 57.4,53.4 r270 bottom
C108 "47pF" CAPC1005X55N#2 57.9,55.3 r0 bottom
C109 "1uF" CAPC1608X90N#2 55.9,51.6 r0 bottom
C110 "15nF" CAPC1005X55N#2 55,57.15 r270 bottom
C111 "47uF" CAPC2013X145N 49.5,53 r90 bottom
C112 "22µF" CAPC1608X90N#2 51.3,53.2 r90 bottom
C113 "100nF" CAPC1005X55N#2 52.5,53.75 r90 bottom
C114 "100uF" CAPC3216X190N 21.395,55 r270 top
C115 "10uF" CAPC2013X135N 46.725,53.9 r180 bottom
C116 "10uF" CAPC2013X135N 46.725,51.9 r180 bottom
C117 "10uF" CAPC2013X135N 46.725,49.9 r180 bottom
C118 "2.2UF" CAPC1608X90N#2 71.4,18.9 r0 top
C119 "10uF" CAPC2013X135N 46.75,60.285 r180 bottom
C120 "1.0uF" CAPC1005X55AL 45.75,30.108 r90 top
C121 "15nF" CAPC1005X55N#2 92.2,23.8 r180 top
C122 "100nF" CAPC1005X55N#2 50.5,37.75 r270 top
C124 "100nF" CAPC1005X55N#2 49.25,37.75 r270 top
C125 "100nF" CAPC1005X55N#2 67.25,59 r180 bottom
C126 "4.7µF" CAPC1005X55AL 68.25,63.75 r0 bottom
C127 "100nF" CAPC1005X55N#2 67.25,60.25 r180 bottom
C128 "100nF" CAPC1005X55N#2 65.25,61.75 r90 bottom
C129 "1.0uF" CAPC1005X55L 79.5,17.807 r90 top
C130 "2.2UF" CAPC1608X90N#2 85.1,58.3 r0 top
C131 "1.0uF" CAPC1005X55L 75,29.2 r90 bottom
C132 "1.0uF" CAPC1005X55L 70.5,28 r180 bottom
C133 "1.0uF" CAPC1005X55L 72.5,28 r180 bottom
C134 "10pF" CAPC1005X55N#2 71,26.25 r90 bottom
C135 "1.0uF" CAPC1005X55L 69.75,26.25 r90 bottom
C136 "1.0uF" CAPC1005X55L 68,26.79 r180 bottom
C137 "10pF" CAPC1005X55N#2 69,22 r180 bottom
C138 "10pF" CAPC1005X55N#2 68,25.54 r180 bottom
C139 "10pF" CAPC1005X55N#2 69,19.5 r180 bottom
C140 "10pF" CAPC1005X55N#2 70.9,23.7 r90 bottom
C141 "1.0uF" CAPC1005X55L 69.767,23.75 r90 bottom
C142 "1.0uF" CAPC1005X55L 68,24.29 r180 bottom
C143 "10pF" CAPC1005X55N#2 68,23.04 r180 bottom
C144 "100nF" CAPC1005X55N#2 42,63.25 r0 bottom
C145 "100nF" CAPC1005X55N#2 42,64.5 r0 bottom
C146 "100nF" CAPC1005X55N#2 44.5,64 r180 bottom
C147 "6.8pF" CAPC1005X55N#2 42.05,66.55 r90 bottom
C149 "1nF" CAPC1005X55N#2 77.5,24.1 r90 top
C150 "100nF" CAPC1005X55N#2 58,36.75 r90 top
C151 "100nF" CAPC1005X55N#2 12.7,37.9 r270 top
C152 "100nF" CAPC1005X55N#2 7.7,37.5 r90 top
C153 "100nF" CAPC1005X55N#2 34,50.25 r180 top
C154 "1nF" CAPC1005X55N#2 40.95,43.25 r0 bottom
C155 "1.0uF" CAPC1005X55N#2 42.5,40 r270 bottom
C156 "100nF" CAPC1005X55N#2 79.8,58.7 r90 top
C157 "100nF" CAPC1005X55N#2 79.9,63.3 r270 top
C158 "1nF" CAPC1005X55N#2 34.3,58.6 r90 bottom
CAD1 "TC2050-IDC-NL" TC_TC2050-IDC-NL 11.25,37.25 r270 bottom
CAD2 "TC2050-IDC-NL" TC_TC2050-IDC-NL 11.5,55.5 r270 bottom
CAD3 "TC2050-IDC-NL" TC_TC2050-IDC-NL 10.5,27.75 r180 bottom
D1 "597-3301-507F" LEDM3020X130N 93.75,31.75 r0 top
D2 "MMSZ5231BT1G" SOD3716X135N 86.5,17.5 r90 bottom
D3 "597-3301-507F" LEDM3020X130N 93.75,29.25 r0 top
D4 "597-3301-507F" LEDM3020X130N 11.65,61.75 r180 top
D6 "ESD9B3.3ST5G" SODFL1006X43AN12 7,51 r90 top
D7 "ESD9B3.3ST5G" SODFL1006X43AN12 5.95,51 r90 top
D10 "ESD9B5.0ST5G" SODFL1006X43N12 54.25,6.25 r270 bottom
D11 "597-3301-507F" LEDM3020X130N 13.25,46.5 r270 top
D12 "597-3401-507F" LEDM3020X130N 93.75,26.75 r0 top
D13 "BAT54CWT1G" SOT65P210X100-3AN 92.522,54.2 r180 top
D14 "BAT54CWT1G" SOT65P210X100-3AN 44.5,65.5 r180 top
FIDUCIAL1 "40mil FID" fiducial_40mil_round 90.8,3.6 r90 bottom
FIDUCIAL2 "40mil FID" fiducial_40mil_round 9.25,17.25 r90 bottom
FIDUCIAL3 "40mil FID" fiducial_40mil_round 18,57.5 r90 bottom
FIDUCIAL4 "40mil FID" fiducial_40mil_round -7.5,65 r90 top
FIDUCIAL5 "40mil FID" fiducial_40mil_round -7.5,2.5 r90 top
FIDUCIAL6 "40mil FID" fiducial_40mil_round 312.5,2.5 r90 top
FIDUCIAL7 "40mil FID" fiducial_40mil_round 16.4,29.7 r90 top
FIDUCIAL8 "40mil FID" fiducial_40mil_round 83,15.5 r90 top
FIDUCIAL9 "40mil FID" fiducial_40mil_round 79.7,66.029 r90 top
FIDUCIAL10 "40mil FID" fiducial_40mil_round -7.5,65 r90 bottom
FIDUCIAL11 "40mil FID" fiducial_40mil_round -7.5,2.5 r90 bottom
FIDUCIAL12 "40mil FID" fiducial_40mil_round 312.5,2.5 r90 bottom
FIL1 "25VDC/6A" FIL_ELKEA 85.5,17 r90 top
H1 "125mil" MH_185_125_NP -7.5,-4 r0 top locked
H2 "125mil" MH_185_125_NP -7.5,72 r0 top locked
H3 "125mil" MH_185_125_NP 312.5,72 r0 top
H4 "125mil" MH_185_125_NP 312.5,-4 r0 top
J1 "CSCD443CCS011B00G" conn_CSCD443CCS011B00G 85.5,12 r90 top
J2 "1x2P" MOLEX_53047-0210#1 98,9.1 r270 top
J3 "1x3P" MOLEX_53047-0310#1 6,61 r90 top
J4 "1x2P" MOLEX_53047-0210#1 98,13.5 r270 top
J5 "1x2P" MOLEX_53047-0210#1 98,18 r270 top
J6 "RJ45" XMULTIPLE_XMG-9799-8821 29.25,8 r0 top locked
J7 "500873-0806" MOLEX_500873-0806 72.5,5.325 r0 bottom
J8 "RJ45" XMULTIPLE_XMG-9799-8821 11,8 r0 top locked
J9 "1x4" MOLEX_53047-0410 6,53.75 r90 top
J10 "1x2" FCI_68002-102HLF 5.75,38.5 r90 top
J11 "FTSH-105-01-F-DV" SAMTEC_FTSH-105-01-F-DV 11.5,55.5 r0 top
J12 "PCIe Minicard" FOXCONN_AS0B221-S68Q-7H 56.75,46.75 r270 bottom locked
J13 "1x14P" MOLEX_53047-1410#1 97.75,64.25 r270 top
J14 "78727-0001" MOLEX_78727-0001 98.7,38 r0 bottom
J15 "KUSBX-AS2N" KYCON_KUSBX-AS2N 48.5,13.5 r0 top
J16 "KMMX-ABSMT5SG-30TR" KYCON_KMMX-ABSMT5 52,1.5 r180 bottom
J17 "1x20P" omron_xf2m-2015-1a 53.75,68.75 r180 top
J18 "MMCX" AMPHENOL_908-22101 96.75,38.9 r270 top
J19 "1x6P" MOLEX_53047-0610#1 98,27.5 r270 top
J20 "1x14P" MOLEX_53047-1410#1 2,7.75 r90 top
J21 "1x40" OMRON_XF2M-4015-1A 23.226,69 r180 top
J22 "3.5mm AUDIO" CUI_SJ1-3515-SMT 73.5,6 r90 top
J23 "SMM-110-02-F-S-P-TR" SAMTEC_SMM-110-02-F-S 19.225,41.925 r270 top
J24 "SMM-110-02-F-S-P-TR" SAMTEC_SMM-110-02-F-S 41.225,41.925 r270 top
J25 "1x3P" MOLEX_53047-0310#2 5.75,32.5 r90 top
J26 "1x8P" MOLEX_53047-0810#1 63.75,10.25 r270 top
J27 "1x6P" MOLEX_53047-0610#2 85.75,70 r0 top
J28 "1x6P" MOLEX_53047-0610#2 76.25,70 r0 top
J29 "1x14P" MOLEX_53047-1410#2 2,46.75 r90 top
J30 "1x14P" MOLEX_53047-1410#2 2,27.25 r90 top
J31 "DF14A-20P-1.25H(25)" HIROSE_DF14A-20P-1.25H 23.226,67.75 r180 bottom
J32 "1x6P" MOLEX_53047-0610#2 5.75,10.25 r90 top
J33 "1x6P" MOLEX_53047-0610#3 63.75,19.75 r270 top
J34 "1x8P" MOLEX_53047-0810#2 64.25,70 r0 top
J35 "640456-2" TE_640456-2 94,9 r0 top
J36 "1x2P" MOLEX_53047-0210#2 41.226,70 r0 top
J37 "FTSH-105-01-F-DV" SAMTEC_FTSH-105-01-F-DV 10.5,29 r90 top
L1 "1.5UH" INDM_SRP4020TA 48.25,57.15 r180 bottom
L2 "220" INDC2013X110N 18.75,27.75 r270 bottom
L3 "220" INDC2013X110N 19.139,45.407 r270 bottom
L4 "0.6nH" INDC0603X33N 92.15,38.9 r180 top
L5 "DLP11SN900" FIL_DLP11S 13.25,62.25 r90 bottom
L6 "220" INDC2013X110N 48.75,18.5 r90 top
L7 "220" INDC2013X110N 46.75,18.5 r90 top
L8 "744231121" FIL_DLW21H 44.5,27.75 r270 bottom
L9 "220" INDC2013X110N 36.3,32.9 r270 top
L10 "744231121" FIL_DLW21H 52.25,6.75 r270 bottom
L11 "744231121" FIL_DLW21H 42.75,27.75 r270 bottom
L12 "220" INDC2013X110N 56.75,18.5 r270 top
L13 "220" INDC2013X110N 58.75,18.5 r270 top
L14 "744231121" FIL_DLW21H 39.75,27.75 r270 bottom
L15 "220" INDC2013X110N 46.75,19.25 r270 bottom
L16 "744231121" FIL_DLW21H 38,27.75 r270 bottom
L17 "220" INDC2013X110N 46,40.25 r90 bottom
L18 "220" INDC2013X110N 9.2,67.131 r0 top
L19 "1.8K" INDC1005X60N 61.75,12 r90 top
L20 "1.8K" INDC1005X60N 61.75,9.25 r90 top
L21 "1.8K" INDC1005X60N 61.75,6.5 r90 top
L22 "1.8K" INDC1005X60N 67.75,14.75 r0 top
L23 "1.8K" INDC1005X60N 67.75,13.75 r0 top
L24 "1.8K" INDC1005X60N 61.75,14.25 r90 top
L28 "220" INDC2013X110N 17.25,54 r270 top
L29 "220" INDC2013X110N 19.25,54 r270 top
L30 "DLP11SN900" FIL_DLP11S 17,62.25 r90 bottom
L31 "DLP11SN900" FIL_DLP11S 20.75,62.25 r90 bottom
L32 "DLP11SN900" FIL_DLP11S 24.5,62.25 r90 bottom
L33 "DLP11SN900" FIL_DLP11S 28.25,62.25 r90 bottom
L34 "220" INDC2013X110N 35,62 r90 bottom
LBL1 "28000351_LABEL" LABEL_10x10 106.459,6.719 r0 top
NT1 "NET TIE" NET_TIE_4mil 68.9,3.3 r180 top net-tie
Q1 "MMBT3906LT1G" SOT95P240X110-3N 88.9,24.9 r180 bottom
Q2 "2N7002T" SOTFL50P160X80_GSD-3N 39.575,28.125 r180 top
Q4 "2N7002T" SOTFL50P160X80_GSD-3N 76.85,22.26 r270 top
Q5 "2N7002T" SOTFL50P160X80_GSD-3N 45.55,38.325 r0 top
Q6 "2N7002T" SOTFL50P160X80_GSD-3N 70.55,57.25 r90 bottom
Q7 "2N7002T" SOTFL50P160X80_GSD-3N 19,39 r90 bottom
Q9 "2N7002T" SOTFL50P160X80_GSD-3N 92.4,51 r0 top
Q10 "2N7002T" SOTFL50P160X80_GSD-3N 40.45,45.25 r0 bottom
Q11 "2N7002T" SOTFL50P160X80_GSD-3N 27.5,59 r90 bottom
R1 "0" RESC1609X55N 81.78,56.67 r270 bottom
R2 "0" RESC1609X55N 80.18,56.67 r270 bottom
R3 "0" RESC1005X40N 13.75,21.25 r0 bottom
R4 "0" RESC1005X40N 13.75,22.5 r0 bottom
R5 "0" RESC0603X33AL 93.75,38.625 r90 top
R6 "0.0" RESC2013X70N 87.9,20.6 r0 top
R7 "10.0K" RESC1005X40N 16.725,35.75 r270 bottom
R8 "100" RESC1005X40N 94.5,12.1 r180 bottom
R9 "0" RESC1005X40N 22.8,50.4 r0 top
R10 "0" RESC1005X40N 22.8,51.6 r0 top
R11 "270" RESC2013X70N 86.5,21.8 r90 bottom
R12 "220" RESC1005X40N 92.7,33.6 r180 top
R13 "10.0K" RESC1005X40N 88.9,22.2 r0 bottom
R14 "470K" RESC1005X40N 89.3,25.1 r0 top
R15 "0" RESC1005X40N 24.25,30.45 r0 top
R16 "0" RESC1005X40N 24.2,28.3 r270 top
R17 "10.0K" RESC1005X40N 46.4,49.6 r180 top
R18 "0" RESC1005X40N 24.3,32.254 r0 top
R19 "0" RESC1005X40N 32.096,32.6 r90 top
R20 "120" RESC1005X40N 89.75,30 r180 bottom
R21 "0" RESC1609X55N 93.1,29.65 r180 bottom
R22 "100K" RESC1005X40N 91.1,24.4 r270 bottom
R23 "120" RESC1005X40N 92.2,24.9 r180 top
R24 "10.0K" RESC1005X40N 65.95,55.84 r0 bottom
R25 "10.0K" RESC1005X40N 63.95,55.84 r180 bottom
R26 "10.0K" RESC1005X40N 28.5,27 r180 bottom
R27 "0" RESC1609X55N 21.3,38.2 r270 bottom
R28 "10.0K" RESC1005X40N 65.95,57.09 r180 bottom
R29 "10.0K" RESC1005X40N 63.95,57.09 r0 bottom
R30 "22.1K" RESC1005X40N 72.25,14.98 r90 top
R31 "10.0K" RESC1005X40N 71,14.98 r90 top
R32 "10.0K" RESC1005X40N 69.75,14.98 r90 top
R33 "10.0K" RESC1005X40N 78.5,15 r90 top
R34 "10.0K" RESC1005X40N 77.25,15 r90 top
R35 "100" RESC1005X40N 76,15 r270 top
R36 "10.0K" RESC1005X40N 7.7,35.3 r270 top
R37 "4.7K" RESC1005X40N 64.25,40.75 r270 bottom
R38 "10.0K" RESC1005X40N 66.2,38.2 r90 bottom
R39 "0" RESC1609X55N 76.4,55.7 r270 bottom
R40 "10.0K" RESC1005X40N 82.95,65.5 r90 bottom
R41 "0" RESC1005X40N 26,63.75 r180 top
R42 "0" RESC1005X40N 72.1,55.7 r0 bottom
R43 "150" RESC1005X40N 33.5,8.25 r90 bottom
R44 "49.9" RESC1005X40N 24.3,23.2 r180 bottom
R45 "49.9" RESC1005X40N 26.7,23.2 r0 bottom
R46 "49.9" RESC1005X40N 23.1,20.3 r180 bottom
R47 "49.9" RESC1005X40N 26.2,20.3 r0 bottom
R48 "0" RESC1609X55N 39.25,21 r90 top
R49 "1.0K" RESC1005X40N 28.25,32.5 r270 bottom
R50 "1.0K" RESC1005X40N 28.5,30.75 r180 bottom
R51 "100K" RESC1005X40N 16.75,39 r270 bottom
R52 "150" RESC1005X40N 36.5,8.25 r270 bottom
R53 "4.7K" RESC1005X40N 28.5,29.5 r0 bottom
R54 "12.1k" RESC1005X40N 21.373,23.709 r90 bottom
R55 "0" RESC3225X60N 42.25,21.775 r270 top
R56 "4.7K" RESC1005X40N 25.623,35.709 r270 bottom
R57 "4.7K" RESC1005X40N 25.75,32.5 r270 bottom
R58 "4.7K" RESC1005X40N 21.873,35.709 r270 bottom
R59 "4.7K" RESC1005X40N 23.25,32.5 r270 bottom
R60 "4.7K" RESC1005X40N 26.873,35.709 r90 bottom
R61 "4.7K" RESC1005X40N 27,32.5 r90 bottom
R62 "4.7K" RESC1005X40N 23.123,35.709 r90 bottom
R63 "4.7K" RESC1005X40N 22,32.5 r90 bottom
R64 "10.0K" RESC1005X40N 30.1,32.2 r180 top
R65 "10.0K" RESC1005X40N 31.9,39.8 r90 bottom
R66 "10.0K" RESC1005X40N 33.1,39.8 r90 bottom
R67 "1M_1%" RESC1005X40N 46,33.5 r270 bottom
R68 "47K" RESC1005X40N 44.25,40 r90 bottom
R69 "100K" RESC1005X40N 40.45,48 r180 bottom
R70 "12.1k" RESC1005X40N 46.2,30.7 r180 bottom
R71 "47K" RESC1005X40N 37.5,40 r270 bottom
R72 "10.0K" RESC1005X40N 36.825,30.625 r0 top
R73 "47K" RESC1005X40N 40,40 r270 bottom
R74 "47K" RESC1005X40N 41.25,40 r270 bottom
R75 "4.7K" RESC1005X40N 39.6,30.3 r0 top
R76 "150" RESC1005X40N 15.25,8.25 r90 bottom
R77 "0" RESC1005X40N 88.65,61.7 r270 top
R78 "10.0K" RESC1005X40N 70,53.5 r180 bottom
R79 "0" RESC1609X55N 17,21 r90 bottom
R80 "0" RESC1005X40N 22.3,30.436 r180 top
R81 "0" RESC1005X40N 84.25,56.25 r180 bottom
R82 "0" RESC1609X55N 45.9,45.1 r270 bottom
R83 "100K" RESC1005X40N 21,20.75 r270 bottom
R84 "0" RESC1005X40N 22.8,45.5 r270 top
R85 "49.9" RESC1005X40N 24.25,41.25 r180 bottom
R86 "49.9" RESC1005X40N 27.25,41.25 r0 bottom
R87 "49.9" RESC1005X40N 24.2,38.3 r180 bottom
R88 "49.9" RESC1005X40N 27.2,38.3 r0 bottom
R89 "0" RESC1005X40N 20.3,30.436 r0 top
R90 "10.0K" RESC1005X40N 28.4,46.5 r180 bottom
R91 "27K" RESC1005X40N 73.4,19.55 r270 top
R92 "12K" RESC1609X55N 70.8,20.4 r0 top
R93 "10.0K" RESC1005X40N 86.1,26.9 r180 bottom
R94 "0" RESC1005X40N 83.2,24.5 r180 bottom
R95 "0" RESC1005X40N 62.75,23 r270 top
R96 "0" RESC1005X40N 62.75,25.25 r90 top
R97 "100K" RESC1005X40N 27.75,20.75 r270 bottom
R98 "0" RESC1005X40N 29,20.75 r90 bottom
R99 "0" RESC1005X40N 19.75,20.75 r90 bottom
R100 "10.0K" RESC1005X40N 46.4,60.7 r180 top
R101 "0" RESC1005X40N 15.5,41.75 r270 top
R102 "0" RESC1005X40N 15.5,39.25 r270 top
R103 "0" RESC1005X40N 64,23 r270 top
R104 "120" RESC1005X40N 86.75,67 r0 bottom
R105 "0" RESC1005X40N 64,25.25 r90 top
R106 "0" RESC1005X40N 65.25,23 r270 top
R107 "0" RESC1005X40N 65.25,25.25 r90 top
R108 "0" RESC1005X40N 66.5,23 r270 top
R109 "2.2K" RESC1005X40N 69,23 r270 top
R110 "2.2K" RESC1005X40N 69,25.25 r90 top
R111 "0" RESC1005X40N 66.5,25.25 r90 top
R112 "10.0K" RESC1005X40N 48,58.4 r270 top
R113 "10.0K" RESC1005X40N 48,56.2 r90 top
R114 "0" RESC1005X40N 67.75,23 r270 top
R115 "0" RESC1005X40N 67.75,25.25 r90 top
R116 "120" RESC1005X40N 92.25,67 r0 bottom
R117 "10.0K" RESC1005X40N 81.2,67.75 r180 top
R118 "0" RESC1005X40N 22.2,28.3 r90 top
R119 "120" RESC1005X40N 12.5,63.75 r180 top
R120 "1.0K" RESC1005X40N 92.3,50.525 r90 bottom
R121 "10.0K" RESC1005X40N 55.1,23.6 r270 top
R122 "10.0K" RESC1005X40N 76.75,66.5 r180 top
R123 "0" RESC1005X40N 85.7,61.8 r270 top
R124 "150" RESC1005X40N 18,8.25 r270 bottom
R125 "0" RESC1005X40N 24.3,34.2 r0 bottom
R126 "10.0K" RESC1005X40N 89.3,24 r180 top
R127 "10.0K" RESC1005X40N 31.9,38.6 r270 top
R128 "10.0K" RESC1005X40N 80.258,21.25 r180 top
R129 "0" RESC1005X40N 15.5,36.25 r90 top
R130 "0" RESC1005X40N 44.75,32.5 r270 top
R131 "0" RESC1005X40N 82,21.25 r90 bottom
R132 "100K" RESC1005X40N 74.6,22.8 r0 top
R133 "120" RESC1005X40N 13.275,49.725 r270 top
R134 "0" RESC1005X40N 45.25,41.5 r90 top
R135 "0" RESC1005X40N 37.75,38.5 r270 top
R136 "0" RESC1005X40N 37.8,50.4 r270 top
R137 "470K" RESC1005X40N 52.25,55.4 r180 bottom
R138 "470K" RESC1005X40N 52.5,57.15 r270 bottom
R139 "100K" RESC1005X40N 53.75,57.15 r270 bottom
R140 "100K" RESC1005X40N 59.1,53 r0 bottom
R141 "0" RESC1005X40N 59.1,54.1 r180 bottom
R142 "2R" RESC1609X55N 59,51.6 r0 bottom
R143 "53.6k" RESC1609X55N 58.25,57.4 r90 bottom
R144 "12K" RESC1609X55N 56.5,57.4 r270 bottom
R145 "10.0K" RESC1005X40N 37.75,43.5 r270 top
R146 "10.0K" RESC1005X40N 15.5,33.5 r90 top
R147 "10.0K" RESC1005X40N 48,54.2 r270 top
R148 "0.0" RESC2013X70N 90.058,20.8 r0 bottom
R149 "0" RESC1005X40N 14.992,34 r180 bottom
R150 "0" RESC1005X40N 15.3,58.7 r0 bottom
R151 "0" RESC1005X40N 15,32.7 r180 bottom
R152 "0" RESC1005X40N 15,51.7 r180 bottom
R153 "10.0K" RESC1005X40N 48,52 r90 top
R154 "4.7K" RESC1005X40N 28.5,49 r0 bottom
R155 "0" RESC1005X40N 32.5,35.25 r90 top
R156 "10.0K" RESC1005X40N 48,47.8 r90 top
R157 "12.1k" RESC1005X40N 21.9,42.3 r0 bottom
R158 "4.7K" RESC1005X40N 24.6,54.2 r0 bottom
R159 "4.7K" RESC1005X40N 25.889,51.407 r270 bottom
R160 "4.7K" RESC1005X40N 22.889,53.907 r270 bottom
R161 "4.7K" RESC1005X40N 22.889,51.407 r270 bottom
R162 "4.7K" RESC1005X40N 24.6,53.2 r180 bottom
R163 "4.7K" RESC1005X40N 27.139,51.407 r90 bottom
R164 "4.7K" RESC1005X40N 21.639,53.907 r90 bottom
R165 "4.7K" RESC1005X40N 21.639,51.407 r90 bottom
R166 "10.0K" RESC1005X40N 48,62.4 r270 top
R167 "0" RESC1005X40N 18.5,20.75 r90 bottom
R168 "10.0K" RESC1005X40N 31.8,62.8 r0 bottom
R169 "10.0K" RESC1005X40N 39.6,63.234 r270 bottom
R170 "10.0K" RESC1005X40N 41,62.1 r180 bottom
R171 "10.0K" RESC1005X40N 37,67.1 r270 top
R172 "10.0K" RESC1005X40N 38.1,64.5 r90 top
R173 "10.0K" RESC1005X40N 39.1,53.9 r270 top
R174 "10.0K" RESC1005X40N 38.475,63.2 r90 bottom
R175 "10.0K" RESC1005X40N 42.5,61.6 r90 bottom
R176 "10.0K" RESC1005X40N 38.534,67.1 r90 top
R177 "10.0K" RESC1005X40N 39.2,64.5 r270 top
R178 "10.0K" RESC1005X40N 37.9,53.9 r90 top
R179 "12K" RESC1609X55N 87.88,59.087 r270 top
R180 "20K" RESC1609X55N 85.38,59.837 r0 top
R181 "0" RESC1005X40N 19.1,28.08 r270 top
R182 "0" RESC1005X40N 92.4,56.6 r0 top
R183 "0" RESC1005X40N 90.25,61.207 r0 top
R184 "0" RESC1005X40N 92.25,61.207 r180 top
R185 "10.0K" RESC1005X40N 77.9,59.9 r180 bottom
R186 "100K" RESC1005X40N 68.6,57.3 r270 bottom
R187 "0" RESC1005X40N 61.5,23 r270 top
R188 "0" RESC1005X40N 61.5,25.25 r90 top
R189 "0" RESC1005X40N 81.66,18.25 r90 bottom
R190 "0" RESC1005X40N 82.91,18.25 r90 bottom
R191 "0" RESC1005X40N 83.2,21.2 r90 bottom
R192 "0" RESC1005X40N 83.5,26.6 r180 bottom
R193 "0" RESC1005X40N 83.2,25.6 r180 bottom
R194 "0" RESC1005X40N 86.1,25 r180 bottom
R195 "0" RESC1005X40N 83.5,27.7 r180 bottom
R196 "2.2K" RESC1005X40N 75,27.5 r90 bottom
R197 "0" RESC1005X40N 69,20.79 r180 bottom
R198 "0" RESC1005X40N 69,18.25 r180 bottom
R199 "0" RESC1005X40N 60.25,23 r270 top
R200 "0" RESC1005X40N 60.25,25.25 r90 top
R201 "0" RESC1005X40N 46.7,65.7 r180 bottom
R202 "10.0K" RESC1005X40N 46.7,66.95 r180 bottom
R203 "0" RESC1005X40N 42.05,67.6 r180 top
R204 "0" RESC1005X40N 42.5,66 r270 top
R205 "0" RESC1005X40N 46.7,68.2 r180 bottom
R206 "0" RESC1609X55N 83.1,23.418 r90 top
R207 "0" RESC1005X40N 23.75,64 r180 top
R208 "0" RESC1005X40N 23.75,62.75 r180 top
R209 "0" RESC1005X40N 23.75,61.5 r180 top
R210 "0" RESC1005X40N 20.75,62.75 r0 top
R211 "0" RESC1005X40N 20.75,64 r0 top
R212 "2.2M" RESC1005X40N 92.5,49.1 r180 top
R213 "316K" RESC1609X55N 8.5,39.6 r180 top
R214 "0" RESC1005X40N 37.208,54.6 r270 bottom
R215 "0" RESC1005X40N 36,54.6 r270 bottom
R216 "0" RESC1005X40N 34.8,54.6 r270 bottom
R217 "0" RESC1005X40N 33.5,54.6 r270 bottom
R218 "0" RESC1005X40N 32.25,54.55 r270 bottom
R219 "0" RESC1005X40N 31,54.6 r270 bottom
R220 "0" RESC1005X40N 29.75,54.75 r270 bottom
R221 "0" RESC1005X40N 28.5,54.75 r270 bottom
R222 "10.0K" RESC1005X40N 46.4,57.9 r180 top
R223 "0" RESC1609X55N 70.5,59 r0 bottom
R224 "0.0" RESC2013X70N 93.6,20.8 r0 bottom
R225 "0" RESC1609X55N 90,18.5 r180 bottom
R226 "0" RESC1609X55N 90,16.9 r180 bottom
R227 "0" RESC1005X40N 58.1,25.8 r180 top
R228 "0" RESC1005X40N 58.1,27 r180 top
R229 "0" RESC1005X40N 56,25.8 r0 top
R230 "0" RESC1005X40N 56,27 r0 top
R231 "10.0K" RESC1005X40N 58.5,44 r270 top
R232 "10.0K" RESC1005X40N 52.75,37.75 r270 top
R233 "10.0K" RESC1005X40N 46.4,56.7 r180 top
R234 "10.0K" RESC1005X40N 46.4,53.7 r180 top
R235 "10.0K" RESC1005X40N 46.4,52.5 r180 top
R236 "10.0K" RESC1005X40N 46.4,48.3 r180 top
R237 "10.0K" RESC1005X40N 46.4,61.9 r180 top
R238 "10.0K" RESC1005X40N 48,50.1 r270 top
R239 "10.0K" RESC1005X40N 48,60.2 r90 top
R240 "10.0K" RESC1005X40N 43.45,48 r180 bottom
R241 "10.0K" RESC1005X40N 61.5,51.7 r90 bottom
R242 "10.0K" RESC1005X40N 44.25,42 r270 bottom
R243 "0" RESC1005X40N 77.6,57.2 r180 top
R244 "0" RESC1005X40N 75.4,59.2 r90 top
R245 "0" RESC1005X40N 77.5,61 r180 top
R246 "0" RESC1005X40N 75.3,62.6 r90 top
R247 "4.7K" RESC1005X40N 57.1,28.1 r0 top
R248 "0" RESC1005X40N 46.4,62.9 r180 bottom
R249 "0" RESC1005X40N 36.7,53.9 r90 top
R250 "0" RESC1609X55N 32.3,61.4 r0 bottom
R251 "10.0K" RESC1005X40N 29.4,58.9 r270 bottom
R252 "100K" RESC1005X40N 28.5,57.2 r90 bottom
R253 "0" RESC1005X40N 5,44.865 r90 bottom
R254 "10.0K" RESC1005X40N 57.6,33.6 r90 top
R255 "0" RESC1005X40N 60.5,18 r90 top
R256 "0" RESC1005X40N 4.158,44.8 r90 top
R257 "33K" RESC1005X40N 8.779,41.6 r180 top
R258 "0" RESC1005X40N 28.25,63.75 r0 top
R259 "0" RESC1005X40N 28.25,62.5 r0 top
R260 "10.0K" RESC1005X40N 59.25,36.75 r90 top
R261 "0.0" RESC2013X70N 94.3,51.5 r270 top
R262 "10.0K" RESC1005X40N 49.2,26.1 r270 top
R263 "0" RESC1005X40N 84.25,67 r180 bottom
R264 "0" RESC1005X40N 89.75,67 r180 bottom
R265 "4.7K" RESC1005X40N 56.6,24 r270 top
R266 "10.0K" RESC1005X40N 37,64.5 r270 top
R267 "1.0K" RESC1005X40N 92.8,63.3 r270 top
R268 "0" RESC1005X40N 4.75,26.85 r0 top
R269 "0" RESC1005X40N 4.75,25.75 r0 top
R270 "1.0K" RESC1005X40N 68,53.5 r0 bottom
R271 "1.0K" RESC1005X40N 79.2,67.75 r0 top
R272 "1.0K" RESC1005X40N 65.6,40.8 r90 bottom
R273 "1.0K" RESC1005X40N 76.75,65.5 r180 top
R274 "0" RESC1005X40N 58.5,24.4 r0 top
R275 "0" RESC1005X40N 58.3,21.4 r180 top
R276 "0" RESC1005X40N 61.5,18 r90 top
R277 "0" RESC1005X40N 67.75,17 r180 top
R278 "0" RESC1005X40N 67.75,16 r180 top
R279 "0.0" RESC2013X70N 81.8,60 r270 bottom
R280 "0.0" RESC2013X70N 51.6,40.95 r0 top
R281 "10.0K" RESC1005X40N 86.75,66.55 r0 top
R282 "0" RESC1005X40N 84.25,57.4 r180 bottom
R283 "1.0K" RESC1005X40N 58.8,33.6 r90 top
SW1 "KSC221JLFS" SW_KSC221J 16.25,22.25 r90 top
SW2 "KSC221JLFS" SW_KSC221J 25.25,22.25 r90 top
SW4 "TDA02H0SB1" SW_TDA02 53.25,44.25 r0 top
TP1 "TESTPOINT" TP0762 91.5,51.75 r180 bottom
TP2 "TESTPOINT" TP0762 89.25,49.25 r180 bottom
TP3 "TESTPOINT" TP0762 89.25,51.75 r0 bottom
TP4 "TESTPOINT" TP0762 93.75,49.25 r90 bottom
TP5 "TESTPOINT" TP0762 73.9,52.2 r0 bottom
TP8 "TESTPOINT" TP0762 91.5,49.245 r90 bottom
TP9 "TESTPOINT" TP0762 17,51.75 r270 bottom
TP10 "TESTPOINT" TP0762 16.25,48.25 r270 bottom
TP11 "TESTPOINT" TP0762 16.25,45.75 r270 bottom
TP12 "TESTPOINT" TP0762 36.75,42.25 r270 bottom
TP13 "TESTPOINT" TP0762 14,31.75 r270 bottom
TP14 "TESTPOINT" TP0762 36,38.75 r270 bottom
TP15 "TESTPOINT" TP0762 15.5,43.75 r270 bottom
TP16 "TESTPOINT" TP0762 83.4,52.8 r90 bottom
U1 "FDMA908PZ" DFN200X200X80-6N 94.25,18.5 r90 bottom
U2 "eMMC_4GB" BGA153C50P14X14_1150X1300X100 67.75,62.75 r90 top
U3 "FDMA908PZ" DFN200X200X80-6N 91.058,20.967 r180 top
U4 "SI2323DS-T1-E3" SOT95P240X110_GSD-3N 75.17,58.92 r270 bottom
U5 "SMBJ5.0A-E3/5B" DIOM5436X244N 91.5,15.25 r180 top
U6 "MAX98089" QFN40P700X700X80-57T560X560N 76.8,22.31 r180 bottom
U7 "SIP32401A" SON50P120X160X60-5T55X91N 93.1,23.6 r180 bottom
U8 "SI2323DS-T1-E3" SOT95P240X110_GSD-3N 19.225,35.75 r90 bottom
U9 "MAX3243EIPW" SOP65P640X120-28N 27.25,37.95 r270 top
U10 "NC7SZ57P6X" SOT65P210X110-6N 58,40 r180 top
U11 "CCWi-i.MX6UL" CC6UL_LGA 75.75,41.5 r270 top locked
U12 "MIC2026" SOIC127P600X175-8N 29.075,28.814 r0 top
U13 "USB2514BI-AEZG" QFN50P600X600X100-37AN 41.25,33.75 r90 bottom
U14 "MIC2026" SOIC127P600X175-8N 32.5,35 r270 bottom
U15 "SI2323DS-T1-E3" SOT95P240X110_GSD-3N 36.825,27.875 r180 top
U16 "LAN8720Ai" QFN50P400X400X100-25 24,28.25 r0 bottom
U17 "AP2202" SOT95P280X145-5N 76.058,19.45 r90 top
U18 "SN65HVD233DR" SOIC127P600X175-8N 86.75,62.5 r90 bottom locked
U19 "SN65HVD233DR" SOIC127P600X175-8N 92.25,62.5 r90 bottom locked
U20 "TPD4E001DRSR" SON95P300X300X80-7N 53.75,18.75 r180 top
U21 "TPD4E001DRSR" SON95P300X300X80-7N 51.6,17.5 r270 bottom
U22 "SI2323DS-T1-E3" SOT95P240X110_GSD-3N 80.258,23.75 r0 top
U23 "MP2316" QFN_MPS_MP2316 55,54.25 r0 bottom
U24 "LAN8720Ai" QFN50P400X400X100-25 24.639,46.907 r0 bottom
U25 "BU90T82" BGA72C65P9X9_700X700X112 40.3,59.15 r90 top
U26 "AP2202" SOT95P280X145-5N 90.88,58.837 r90 top
U27 "CC6UL-SBC-IOEXP" QFN50P700X700X100-49N 52,32.25 r270 top locked
U28 "NTAG_2KB" NXP_XQFN8 43.8,66.05 r270 bottom
U30 "NC7S00P5X" SOT65P210X110-5N 10.2,37.5 r270 top
U31 "SN74CB3Q3245PWR" SOP65P640X120-20N 30.5,54.75 r270 top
